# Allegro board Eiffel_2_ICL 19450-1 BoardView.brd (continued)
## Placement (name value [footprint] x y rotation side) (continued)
R24006  10KR2F-2-GP  [R402H16]  70.95 9.16 0 bottom
R24007  10KR2F-2-GP  [R402H16]  77.86 18.36 0 bottom
R24008  33R2J-2-GP  [R402H16]  88.98 7.2 270 bottom
R24009  0R0402-PAD-2-GP  [0R0402-PAD-1]  87.37 20.84 180 bottom
R24010  17K8R2F-GP  [R402H16]  76.14 28.77 180 top
R24011  10KR2J-3-GP  [R402H16]  70.97 20.56 270 top
R24012  0R2J-2-GP  [R402H16]  97.81 10.76 90 top
R24013  10KR2J-3-GP  [R402H16]  70.97 19.51 90 top
R24014  1KR2F-3-GP  [R402H16]  83.37 18.28 90 bottom
R24015  0R2J-2-GP  [R402H16]  78.55 29.84 90 bottom
R24016  0R2J-2-GP  [R402H16]  85.97 23.73 0 bottom
R24017  10KR2J-3-GP  [R402H16]  81.84 28.77 270 bottom
R24018  100KR2J-1-GP  [R402H16]  73.26 22.34 180 bottom
R24019  0R2J-2-GP  [R402H16]  84.81 9.85 180 bottom
R24020  10KR2F-2-GP  [R402H16]  77.22 16.23 270 bottom
R24021  10KR2J-3-GP  [R402H16]  96.14 15.52 90 top
R24022  0R0402-PAD-2-GP  [0R0402-PAD-1]  84.53 28.4 180 top
R24023  0R2J-2-GP  [R402H16]  93.07 23.23 90 top
R24024  0R0402-PAD-2-GP  [0R0402-PAD-1]  95.49 12.99 270 top
R24025  0R0402-PAD-2-GP  [0R0402-PAD-1]  95.49 11.89 270 top
R24026  100R2F-L1-GP-U  [R402H14]  73.46 28.27 270 bottom
R24027  SCD1U16V2KX-3GP  [C402H22]  76.85 20.6 180 bottom
R24028  10KR2J-3-GP  [R402H16]  80.8 5.68 270 bottom
R24029  1KR2J-1-GP  [R402H16]  92.19 24.51 270 bottom
R24030  10KR2J-3-GP  [R402H16]  71.05 6.13 0 bottom
R24031  0R0402-PAD-2-GP  [0R0402-PAD-1]  74.47 5.42 180 top
R24032  0R0402-PAD-2-GP  [0R0402-PAD-1]  96.85 6 180 top
R24033  0R0402-PAD-2-GP  [0R0402-PAD-1]  86.32 20.84 180 bottom
R24034  0R0402-PAD-2-GP  [0R0402-PAD-1]  98.31 16.37 270 top
R24035  0R0805-PAD-2-GP-U  [0R0805-PAD-1-U]  82.14 8.86 180 bottom
R24036  0R0402-PAD-2-GP  [0R0402-PAD-1]  95.49 14.09 270 top
R24037  0R0402-PAD-2-GP  [0R0402-PAD-1]  85.19 20.84 180 bottom
R24038  10KR2J-3-GP  [R402H16]  78.9 5.55 90 bottom
R24039  10KR2J-3-GP  [R402H16]  84.25 7.89 180 bottom
R24040  0R0402-PAD-2-GP  [0R0402-PAD-1]  86.06 5.99 0 bottom
R24041  0R2J-2-GP  [R402H16]  75.56 5.42 180 top
R24042  0R2J-2-GP  [R402H16]  93.5 22.15 90 top
R24044  10KR2J-3-GP  [R402H16]  89.88 28.98 180 top
R24045  10KR2F-2-GP  [R402H16]  82.07 12.42 180 bottom
R24046  10KR2F-2-GP  [R402H16]  78.03 24.49 90 bottom
R24047  0R2J-2-GP  [R402H16]  97.8 11.88 90 top
R24048  10KR2J-3-GP  [R402H16]  89.89 20.26 90 bottom
R24049  10KR2J-3-GP  [R402H16]  89.89 21.32 90 bottom
R24051  330R2J-3-GP  [R402H16]  80.57 29.75 90 top
R24052  0R2J-2-GP  [R402H16]  97.79 9.65 90 top
R24053  0R2J-2-GP  [R402H16]  96.16 21.09 90 top
R24054  10KR2F-2-GP  [R402H16]  73.24 16.3 90 bottom
R24055  10KR2J-3-GP  [R402H16]  71.55 17.28 270 top
R24056  10KR2J-3-GP  [R402H16]  84.97 17.88 180 bottom
R24057  0R0402-PAD-2-GP  [0R0402-PAD-1]  86.62 29.9 180 top
R24058  0R0402-PAD-2-GP  [0R0402-PAD-1]  99.99 19.12 180 bottom
R24059  10KR2J-3-GP  [R402H16]  96 23.67 270 top
R24060  1KR2J-1-GP  [R402H16]  80.14 9.96 270 bottom
R24061  10KR2F-2-GP  [R402H16]  74.08 27.06 90 top
R24062  20KR2J-L2-GP  [R402H16]  94.93 6.01 180 top
R24063  10KR2J-3-GP  [R402H16]  85.06 29.94 90 top
R24064  33R2J-2-GP  [R402H16]  96.15 16.55 90 top
R24065  10KR2J-3-GP  [R402H16]  70.97 21.63 270 top
R24066  4K7R2J-2-GP  [R402H16]  88.25 24.46 180 bottom
R24067  0R2J-2-GP  [R402H16]  84.5 25.17 270 bottom
R24068  0R0402-PAD-2-GP  [0R0402-PAD-1]  90.93 28.4 180 top
R24069  10KR2J-3-GP  [R402H16]  85.98 9.87 0 bottom
R24070  0R2J-2-GP  [R402H16]  81.29 5.25 180 top
R24071  10KR2J-3-GP  [R402H16]  78.9 6.57 90 bottom
R24072  10KR2J-3-GP  [R402H16]  70.6 7.61 270 bottom
R24073  10KR2F-2-GP  [R402H16]  78.7 20.61 180 bottom
R24074  0R0402-PAD-2-GP  [0R0402-PAD-1]  72 25.62 270 top
R24075  10KR2J-3-GP  [R402H16]  70.89 11.64 270 top
R24076  10KR2F-2-GP  [R402H16]  79.9 13.47 90 bottom
R24077  10KR2F-2-GP  [R402H16]  80.84 18.37 0 bottom
R24078  10KR2J-3-GP  [R402H16]  88.81 28.98 180 top
R24079  10KR2J-3-GP  [R402H16]  96.06 8.11 0 top
R24081  0R2J-2-GP  [R402H16]  76.6 6 180 top
R24082  0R0402-PAD-2-GP  [0R0402-PAD-1]  95.45 10.77 270 top
R24084  10KR2J-3-GP  [R402H16]  70.96 22.69 90 top
R24085  0R0402-PAD-2-GP  [0R0402-PAD-1]  95.45 9.66 270 top
R24086  10KR2F-2-GP  [R402H16]  72.53 7.64 270 bottom
R24087  0R2J-2-GP  [R402H16]  98.35 20.84 180 top
R24088  4K7R2J-2-GP  [R402H16]  98.47 18.74 90 bottom
R24089  33R2J-2-GP  [R402H16]  87.37 6.15 0 bottom
R24091  0R0402-PAD-2-GP  [0R0402-PAD-1]  76.4 18.76 90 bottom
R24092  0R2J-2-GP  [R402H16]  97.81 14.01 90 top
R24093  0R2J-2-GP  [R402H16]  97.81 12.97 90 top
R24094  0R0402-PAD-2-GP  [0R0402-PAD-1]  73.02 7.42 270 top
R24095  10KR2J-3-GP  [R402H16]  97.63 18.99 90 top
R24096  95K3R2F-GP  [R402H16]  74.35 29.22 270 top
R24097  20KR2J-L2-GP  [R402H16]  71.73 21.89 90 bottom
R24098  10KR2F-2-GP  [R402H16]  79.8 18.38 0 bottom
R24099  10KR2J-3-GP  [R402H16]  85.58 28.4 180 top
R24100  4K7R2F-GP  [R402H16]  70.68 18.61 180 bottom
R24101  10KR2J-3-GP  [R402H16]  70.97 18.44 90 top
R24102  33R2J-2-GP  [R402H16]  84.99 6.01 180 bottom
R24103  0R5J-5-GP  [R805H24]  89.6 17.85 0 bottom
R24104  100KR2J-1-GP  [R402H16]  97.56 17.97 270 top
R24105  33R2J-2-GP  [R402H16]  91.48 5.98 270 bottom
R24106  33R2J-2-GP  [R402H16]  88.99 6.16 90 bottom
R24107  1KR2J-1-GP  [R402H16]  79.05 30.16 180 top
R24108  10KR2J-3-GP  [R402H16]  89.89 22.4 90 bottom
R24109  10KR2F-2-GP  [R402H16]  69.1 9.17 0 bottom
R24110  100KR2J-1-GP  [R402H16]  96 22.64 90 top
R24111  10KR2J-3-GP  [R402H16]  89.99 14.64 270 bottom
R24112  1KR2J-1-GP  [R402H16]  91.91 7.5 180 bottom
R24113  0R0402-PAD-2-GP  [0R0402-PAD-1]  82.55 29.42 180 top
R24114  10KR2F-2-GP  [R402H16]  79.74 28.81 90 bottom
R24115  10KR2F-2-GP  [R402H16]  80.24 11.29 90 bottom
R24116  10KR2J-3-GP  [R402H16]  95 8.11 0 top
R24117  4K7R2J-2-GP  [R402H16]  95.03 23.38 270 bottom
R24118  4K7R2J-2-GP  [R402H16]  95.69 25.74 270 top
R24119  0R0402-PAD-2-GP  [0R0402-PAD-1]  95.69 26.78 90 top
R24120  0R0402-PAD-2-GP  [0R0402-PAD-1]  91.47 26.97 180 bottom
R24121  10KR2J-3-GP  [R402H16]  70.42 16.24 270 top
R24924  499R2F-2-GP  [R402H16]  169.1 74.09 270 bottom
RC4502  SCD1U25V2KX-L-GP  [C402H22]  101.57 77.36 90 top
RJ1  SKT-RJ45-LED-60-GP  [23-01122-2A03-B]  70.5 47.05 180 top
RN303  SRN51J-GP  [SMD-ARES4H18]  170 68.42 0 bottom
RN1201  SRN1KJ-7-GP  [SMD-ARES4H18]  256.01 33.58 180 bottom
RN1301  SRN1KJ-7-GP  [SMD-ARES4H18]  241.01 32.5 180 bottom
RN1804  SRN20KJ-1-GP  [SMD-ARES4H20]  204.05 19.12 180 bottom
RN1810  SRN2K2J-1-GP  [ARES2H16]  173.87 10.94 0 bottom
RN1811  SRN2K2J-1-GP  [ARES2H16]  176.83 6.6 270 top
RN1812  SRN2K2J-4-GP  [ARES8-CN24-UH20]  169.32 20.11 270 bottom
RN1914  SRN2K2J-1-GP  [ARES2H16]  198.24 16.52 90 bottom
RN1915  SRN2K2J-1-GP  [ARES2H16]  198.24 14.34 90 bottom
RN2201  SRN100KJ-6-GP  [SMD-ARES4]  186.4 6.89 0 bottom
RN2402  SRN10KJ-5-GP  [ARES2H18]  92.93 29.8 90 bottom
RN2403  SRN10KJ-5-GP  [ARES2H18]  70.95 13.7 0 top
RN2404  SRN10KJ-5-GP  [ARES2H18]  87.05 17.8 270 bottom
RN2405  SRN10KJ-5-GP  [ARES2H18]  88.08 9.23 270 bottom
RN2703  SRN4K7J-8-GP  [SMD-ARES4H18]  29.64 80.86 270 top
RN4001  SRN10KJ-5-GP  [ARES2H18]  215.59 9.02 90 bottom
RN4002  SRN10KJ-5-GP  [ARES2H18]  203.62 75.55 270 bottom
RN5702  SRN2K2J-5-GP  [SMD-ARES4H18]  41.02 59.56 90 bottom
RN6119  SRN10KJ-5-GP  [ARES2H18]  130.8 9.65 90 top
RN6120  SRN47K-2-GP-U  [SMD-ARES4H18]  102.63 11.27 180 top
RT2401  NTC-10K-19-GP-U  [NTC-402H22-U]  132.79 58.38 90 top
RT2402  NTC-10K-19-GP-U  [NTC-402H22-U]  80.56 28.65 90 top
SATA1  SKT-SATA7P-15P-163-GP  [C166KK-12209-L]  2.8 63.5 270 top
SPK1  ACES-CON4-95-GP  [87212-0044N-W01]  4 15 270 top
TP602  TPAD28-2-GP  [TPAD28]  174.01 51.61 270 bottom
TP603  TPAD28-2-GP  [TPAD28]  173.8 49.64 270 bottom
TP604  TPAD28-2-GP  [TPAD28]  176.06 51.97 180 bottom
TP605  TPAD28-2-GP  [TPAD28]  175.8 50.06 270 bottom
TP607  TPAD28-2-GP  [TPAD28]  181.67 33.69 180 bottom
TP608  TPAD28-2-GP  [TPAD28]  166.22 74.4 270 top
TP609  TPAD28-2-GP  [TPAD28]  164.56 74.4 270 top
TP619  TPAD28-2-GP  [TPAD28]  174.88 32.13 270 bottom
TP808  TPAD28-2-GP  [TPAD28]  170.72 63.12 180 bottom
TP1611  TPAD28-2-GP  [TPAD28]  191.48 36.76 180 bottom
TP1702  TPAD28-2-GP  [TPAD28]  167.86 41.04 180 bottom
TP2111  TPAD28-2-GP  [TPAD28]  182.45 26.69 180 bottom
TP4402  TPAD14-OP-GP  [TPAD14-OP]  104.59 12.19 0 top
TP9901  TPAD28-2-GP  [TPAD28]  171.63 67.94 180 bottom
TP9902  TPAD28-2-GP  [TPAD28]  172.97 66.11 180 bottom
TP9904  TPAD28-2-GP  [TPAD28]  178.51 29.83 180 bottom
TP9905  TPAD28-2-GP  [TPAD28]  162.09 70.11 0 top
TP9906  TPAD28-2-GP  [TPAD28]  168.96 65.93 180 bottom
TP9907  TPAD28-2-GP  [TPAD28]  170.16 64.82 180 bottom
TP9908  TPAD28-2-GP  [TPAD28]  166.1 68.22 0 top
TP9909  TPAD28-2-GP  [TPAD28]  168.87 64.56 180 bottom
TP9910  TPAD28-2-GP  [TPAD28]  171.21 66.28 180 bottom
TSMT1  RTD2136N-CGT-GP  [QFN48J6-G4D55H40]  35.74 25.47 0 bottom
U2401  W25X10CLSNIG-GP  [SOIC8H69]  75.12 12.31 270 bottom
U2501  MX25L12872FM2I-10G-GP  [SOIC8-1H86]  200.18 9.79 90 top
U2504  SKT-91960-0084L-GP  [SKT-SOIC8-1H211]  200.18 9.79 270 top
U2601  APL5606AKI-TRG-GP  [SOIC8H69]  254.23 4.55 270 bottom
U2701  ALC256M-CG-GP  [QFN48J6-G465H40]  31.42 71.64 270 top
U3101  AZC199-04SDR7G-1-GP  [SOT-6-1H58]  68.25 68.26 180 top
U3102  AZC199-04SDR7G-1-GP  [SOT-6-1H58]  74.09 68.34 180 top
U3103  RT9742CGJ5-GP  [SOT-23-5H40]  58.39 77.36 180 top
U3301  RTS5176-GR-GP  [QFN24-G2D5H40-U]  36.39 95.74 0 bottom
U3401  RT9742CGJ5-GP  [SOT-23-5H40]  37.36 57.56 0 top
U3402  RT9742CGJ5-GP  [SOT-23-5H40]  40.93 56.55 0 top
U3503  RT9742CGJ5-GP  [SOT-23-5H40]  77.38 79.91 180 top
U3504  RT9742CGJ5-GP  [SOT-23-5H40]  200.6 96.32 270 top
U4003  TPS22976DPUR-GP  [SON14J3020-G2610H34]  46.28 82.01 180 bottom
U4007  G5027CRD1D-GP-U  [DFN8F3-G2517H32]  190.47 13.07 0 bottom
U4009  TC7SZ08FU-LJ-CT-GP  [SC70-5H44]  185.83 11.46 180 bottom
U4010  G5027CRD1D-GP-U  [DFN8F3-G2517H32]  151.71 23.77 90 bottom
U4011  G5027CRD1D-GP-U  [DFN8F3-G2517H32]  151.85 18.13 90 bottom
U4012  G5027CRD1D-GP-U  [DFN8F3-G2517H32]  162.1 47.6 90 top
U4013  74LVC1G07GW-GP  [SC70-5H44]  163.78 18.77 0 bottom
U4020  SN74AUP1G08DCKR-GP  [SC70-5H44]  117.86 17.86 270 bottom
U4303  INA199A3DCKR-GP  [SC70-6H44]  90.08 31.46 90 top
U5301  G5027CRD1D-GP-U  [DFN8F3-G2517H32]  19 79.96 90 top
U5501  OZ554LN-A-0-TR-GP  [QFN20-G2D1H34]  18.65 28.65 270 top
U5504  RT9742CGJ5-GP  [SOT-23-5H40]  66.75 17.89 180 bottom
U5602  M24C64-RMN6TP-2-GP  [SOIC8H69]  53.35 15.5 270 bottom
USB3R1  SKT-USB11-153-GP  [SKT-USB11-138166]  60 97.08 180 top
USB3R2  SKT-USB11-153-GP  [SKT-USB11-138166]  189 97.08 180 top
USB3R3  SKT-USB11-267-GP  [SKT-USB11-160090-3-U]  30.94 41.04 270 top
USB3R4  SKT-USB11-267-GP  [SKT-USB11-160090-3-U]  42.44 41.04 270 top
X1801  XTAL-32D768KHZ-98-GP  [SMD49-12H34]  195.39 21.01 90 bottom
X1802  XTAL-38D4MHZ-28-GP  [OSC-3225-4P-4H36]  172.68 15.93 0 top
X3101  XTAL-25MHZ-359-GP  [SMD-OSC38H32]  70.99 80.94 270 bottom
XF3101  XFORM-24P-19-GP  [XFORM24C1510H168]  70.78 59.55 0 top

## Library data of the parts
AUDS1 = J1100D-C6DH-0002R: tolerance: 022.10002.0C41
BTT1 = 40-42087-00211RHF-WH-U1: tolerance: 062.70001.0081
C501 C1271 C1281 C1302 C1338 C2202 C2214 C2502 C2707 C2709 C2710 C2716 C2719 C2725 C4030 PC5110 PC5406 PC5407 = C402H22: tolerance: 78.10421.L0L
C701 C2217 C2424 C2503 C4048 C4049 C4302 C4303 C5503 C5510 C5512 C6105-C6107 C6109 EC6901-EC6905 EC6918-EC6923 FC9085-FC9092 PC4501 PC4505 PC4511-PC4515 PC4601 PC4604 PC4607-PC4611 PC5003-PC5005 PC5013 PC5101 PC5111 PC5205 PC5314 PC5320 PC5404 PC5405 = C402H22: tolerance: 78.10422.5FL
C702 C1325 C2218 C2403 C2417 C2423 C2605 C5501 C5506 PC4612 PC5204 = C402H22: tolerance: 78.10134.1FL
C703 C2219 = C402H24: tolerance: 78.12034.1FL
C1101 C1109-C1113 C2706 C2708 C2711 C4011 C4014 C4053 C4060 C4070 C4085 C5303 C5550 C5611 C6104 C6108 C6304 C6342 = C603H38: tolerance: 78.10610.5BL
C1102-C1107 C1114 C1115 C1119-C1122 C1125-C1129 C1216-C1220 C1222 C1223 C1235-C1237 C1251 C1252 C1314 C1315 C1319 C1322 C1331-C1336 C1340 C1341 C1820 C1821 C2204 C2206 C2215 C2418 C2419 C2421 C2422 C2425 C2507 C3141 C3155 C3301 C3302 C3405 C3515 C3524 C4009 C4012 C4015-C4017 C4024 C4069 C4093 C5301 C5527 C5554 PC5103 PC5108 PC5109 PC5116 PC5206 PC5401 = C402H22: tolerance: 78.10523.5FL
C1108 = C603H40: tolerance: 78.4761T.5BL
C1116-C1118 C2405 C2408 C2420 C2603 C3004 C3153 C3404 C3407 C3409 C3417 C3418 C3423 C3517 C3518 C3520 C3522 C3523 C3526 C5556 C5616 PC1002-PC1014 PC1026-PC1032 PC1042-PC1059 PC5117-PC5122 PC5201-PC5203 PC5301 PC5303 PC5305-PC5307 = C603H40: tolerance: 78.22610.5BL
C1205-C1209 C1213-C1215 C1232 C1234 C1238 C1250 C1312 C1313 C1316-C1318 C1320 C1321 C1327 C1329 C1330 C1342 C1343 C2501 C2702 C2712-C2714 C2717 C2718 C2720 PC5402 PC5403 PC5410-PC5412 = C603H38: tolerance: 78.10610.L0L
C1221 C1328 = C402H22: tolerance: 78.22321.2FL
C1272 C1339 C2213 C2703-C2705 PC4603 = C603H36: tolerance: 78.22523.L1L
C1701 C1705 C1823 C2207 C2402 C2404 C2406 C2407 C2409-C2416 C2426 C2427 C2602 C2907 C2908 C2910 C3002 C3005 C3006 C3103 C3106 C3118 C3119 C3128-C3134 C3137-C3140 C3142 C3143 C3145 C3146 C3151 C3154 C3304 C3306 C3308 C3312-C3314 C3406 C3411-C3416 C3513 C3514 C3516 C3521 C4001 C4013 C4018-C4020 C4025 C4501 C4502 C5304 C5528 C5545 C5551 C5559 C5601-C5607 C5609 C5610 C5612-C5615 C5618-C5620 C5701-C5705 C5707-C5709 C5714 C5721 C5722 C6001 C6101 C6102 C6303 C6305 C6341 C6345 EC6906-EC6910 EC6913-EC6917 PC5207 R24027 = C402H22: tolerance: 78.10421.2FL
C1801 C1802 = C402H22: tolerance: 77P4825AA
C1805 C1806 = C402H22: tolerance: 78.15034.1FL
C1904 C2726 = C402H22: tolerance: 78.33034.1FL
C2201 C2203 C2208-C2212 PC5001 PC5002 = C402H22: tolerance: 78.10523.L2L
C2205 C2601 C2604 C3007 C3102 C3135 C3136 C3147 C3303 C3305 C3307 C3309 PC5302 = C603H36: tolerance: 78.47520.5BL
C2216 = C603H40: tolerance: 078.47610.05BL
C2401 = C603H36: tolerance: 78.22523.5BL
C2701 C2715 C2723 C2724 PC4602 = C603H36: tolerance: 78.47520.L0L
C2911 PC5010 = C402H22: tolerance: 78.22224.2FL
C3001 C5505 C5520 C6003-C6006 C6401 = C402H22: tolerance: 78.10324.2FL
C3008 C3009 C6103 C6301 = C402H22: tolerance: 78.10034.1FL
C3125 = C1206H71: tolerance: 78.1022S.22L
C3126 C3127 FC9001-FC9012 PC5112 = C402H22: tolerance: 78.18034.1FL
C3152 C4007 C4008 C4304 C5515 EC2902-EC2905 EC5501-EC5503 EC6401 EC6402 PC5104 = C402H22: tolerance: 78.10224.2FL
C3401 EC4302 PC4302 = C603H36: tolerance: 78.10424.2BL
C3501 C3502 = C402H22: tolerance: 78.22423.5FL
C4026 = C402H22: tolerance: 78.10421.2FLLL
C4061 C4062 C4072 C5302 = C402H22: tolerance: 78.10421.2FLDL
C5502 C5511 EC4301 PC4301 = C603H32: tolerance: 78.10524.5BL
C5504 = C805H54: tolerance: 78.47522.51L
C5507 C5508 C5513 C5514 C5516-C5519 C5521-C5526 C5529-C5534 EC3321-EC3328 = C402H22: tolerance: 78.5R074.1FL
C5509 PC4606 = C603H36: tolerance: 78.47422.5BL
C5536 C5541 C5608 C5617 C6002 PC4502-PC4504 PC4506-PC4510 PC5006-PC5008 PC5102 PC5105-PC5107 PC5114 PC5115 PC5315 PC5316 = C805H56: tolerance: 78.10622.51L
C5537-C5540 C5542 = C1206H71: tolerance: 78.10525.22L
C5544 = C603H36: tolerance: 78.33135.1BL
C5621 PC4516 PC4517 = C402-TO0D2H26: tolerance: 78.47510.5FL
C5713 PC5011 = C402H22: tolerance: 78.47124.2FL
C6306-C6311 C6331 C6332 = C402H22: tolerance: 78.22423.L2L
CAM1 = 51290-0084N-W01: tolerance: 020.F1064.0008
CMOS1 = SKRBAJF010: tolerance: 62.40089.071
CNVBD1 = 51290-0124N-W01: tolerance: 020.F1064.0012
CPU1 = BGA1526M2550-1H51: tolerance: ZZ.00CPU.221
CRS1 = 156-5001902601: tolerance: 62.10051.H51
D2401-D2403 D2701 ED2901-ED2905 = SOT23-2D4-312H46: tolerance: 75.05125.07D
D2501 D4004 D4005 = SOT23-2D4-312H44: tolerance: 75.00054.T7D
D3101 = SOD323AKH38: tolerance: 83.R5003.H8H
D3102 = SOD-523-4H28: tolerance: 75.05125.070
D4302 = SOT-323H40: tolerance: 83.00070.F11
D5301 = SOD323AKH38: tolerance: 83.00355.D1F
D5501 = D4724AKH44: tolerance: 83.3R010.C8M
D5701 = SOT23-2D4-312H44: tolerance: 75.00056.07D
D6301 D6903 D6904 ED6902 = SOD882-10D6-1H20: tolerance: 83.05725.0A0
DBGH1 = 50228-0147N-W01: tolerance: 20.F1637.014
DCIN1 = 2DC3012-005111F: tolerance: 022.10015.0481
DIMM1 = ASAA821-E8RB0-7H: tolerance: 062.10011.01G1
DIMM2 = ASAA821-H4RB5-7H: tolerance: 062.10011.0P91
EC1720 = C402H22: tolerance: 78.22034.L1L
EC1801 EC1802 PC5012 = C402H22: tolerance: 78.22034.1FL
EC2909-EC2913 PC4701 PC4708 = C402H22: tolerance: 78.10224.L1L
EC3101-EC3108 = C402H22: tolerance: 78.6R074.1FL
ECIO1 = LQFP128H63: tolerance: 071.08637.000G
ED3002 ED3401 ED3502 ED3505 ED6101 = SOT-6H58: tolerance: 075.53456.000C
ED3101-ED3103 = SOT23-2D4-312H44: tolerance: 75.00099.O7D
ED3402 ED3403 ED3501 ED3504 ED5701 ED5702 ED6001 = DFN10G2510H22: tolerance: 075.01043.0073
ED4301 = DO214AAAK-1121H97: tolerance: 83.P6SMB.AAG
ED5703 = SOT-6H58: tolerance: 075.09904.0A7C
EL3001 EL3401 EL3402 EL3503 EL3509 EL6103 = DUMMY-LD65D85-4PH20: tolerance: ZZ.PAD02.091
EL3403-EL3406 EL3501 EL3502 EL3507 EL3508 EL5701-EL5704 EL6001 EL6002 = L125100-4P-5H24: tolerance: 68.24500.201
ER1801 ER1802 PR4511 PR4634 PR4636 PR5113 PR5114 PR5317 PR5326 PR5401 PR5413 PR5423 R511 R706 R809 R1302 R1510 R1709 R1720 R1722 R1727 R2204 R2208 R2519 R2605 R2702-R2706 R2710 R2721 R2722 R2732 R2733 R2754 R2766 R2909 R2922-R2924 R3115 R3141 R3142 R3154 R3303-R3305 R4014 R4018 R4035 R4047 R4051 R4054 R4602-R4604 R5536 R5601 R5607 R5625 R5626 R5731 R6105 R6107 R6109 R6110 R6133 R6134 R6141 R6302 R6303 R6311 R6313 R6314 R10013 R10014 R10021 R24004 R24009 R24022 R24024 R24025 R24031-R24034 R24036 R24037 R24040 R24057 R24058 R24068 R24074 R24082 R24085 R24091 R24094 R24113 R24119 R24120 = 0R0402-PAD-1: tolerance: ZZ.00PAD.M11
F3001 F3002 F5701 = POLYSW-2114H30: tolerance: 69.48001.081
F5501 = POLYSW-4633-UH43: tolerance: 69.50007.A31
F6001 = POLYSW-2114H30: tolerance: 069.50003.0001
FANC1 = 3801-Q03S-01R: tolerance: 20.D0246.103
G2401 G6401 = CON2C-U: tolerance: ZZ.CON2C.XXX
G2530 = CON2O-U: tolerance: ZZ.CON2O.XXX
GDT1 = TVS5436-1121H105: tolerance: 069.A0007.0001
H1-H5 = GEN315R158-8-F-C-S-U: tolerance: ZZ.SCREW.541
HDMI1 = SKT-HDMI22-148070: tolerance: 062.10012.0401
HS5 = STF256R109H124: tolerance: 334.0350J.0001
HS6 = STF256R113-UH286: tolerance: 334.08002.0001
HS7 = STF236R128H34: tolerance: 34.4QP10.001
L2401 L2903-L2907 L2910 L3302 L6405 L6406 = L402-TO0D2H24: tolerance: 068.00049.0041
L3101 = L3030-3009-2H40: tolerance: 68.4R71H.10H
L3102-L3105 L3301 = L125100-4P-4H24: tolerance: 68.00396.001
L5501 = L125100-4P-1H37: tolerance: 68.01012.201
L5502 = L8080-6020H158: tolerance: 068.33010.1061
L5601 L5602 = L402H24: tolerance: 068.00005.0051
L6401 = L603H38: tolerance: 68.00335.091
LAN1 = QFN32J4-G2D85H36: tolerance: 71.08111.U03
LED1 = LED3020-3P-6H44: tolerance: 83.01222.X80
LED683-LED685 = LED1608-1A2KH40: tolerance: 83.01921.S70
LVDS1 = 50524-0300N-001: tolerance: 020.K0037.0030
MFG1 = MSS3-Q-T-R: tolerance: 62.40018.641
NGFFE1 = AS0BC21-S40BE-7H: tolerance: 062.10003.0611
NGFFM1 = APCI0096-P003A: tolerance: 062.10003.0E81
PC4605 = C603H40: tolerance: 78.22422.2BL
PC4613 PC5312 = C402H22: tolerance: 78.22124.2FL
PC4624 PC5308 RC4502 = C402H22: tolerance: 78.10422.L1L
PC4702-PC4707 PC4709 PC4710 = C805H56: tolerance: 78.10622.LAL
PC5113 = C402H22: tolerance: 78.47322.2FL
PC5313 = C402H22: tolerance: 78.10322.2FL
PG4501-PG4514 PG4516-PG4518 PG4520 PG4529-PG4533 PG4601 PG4701-PG4712 PG5001-PG5006 PG5101-PG5104 PG5201-PG5204 PG5301 PG5302 PG5304 PG5305 PG5315 PG5318 PG5320 PG5401 PG5402 = GAP-CLOSE-PWR-3: tolerance: ZZ.CLOSE.001
PL4501 PL4502 = L7066-1830-UH119: tolerance: 68.2R210.20B
PL4701 PL4702 PL5001 = L7366-1930H158: tolerance: 68.R1510.20A
PL5101 = L7066-1830-UH119: tolerance: 68.1R01A.20B
PL5301 = L4947-1115H119: tolerance: 68.1R010.20R
PL5401 = L2520-D620H48: tolerance: 068.1R010.1131
PL5402 = L2520-D620H48: tolerance: 68.1001S.10K
PR4301 R1820 = R402H16: tolerance: 64.20035.6DL
PR4302 PR4303 R5505 R24062 R24097 = R402H16: tolerance: 63.20334.1DL
PR4304 PR5110 PR5204 PR5420 PR5421 R403 R1503 R1504 R1506 R1507 R1531 R1534 R1706 R1712 R1713 R1718 R1726 R1728 R1729 R1840-R1844 R2108 R2201 R2209 R2210 R3404 R4052 R4053 R4057 R5602 R5624 R5730 R24018 R24104 R24110 = R402H16: tolerance: 63.10434.1DL
PR4305 = R2512H32: tolerance: 64.R0105.97L
PR4501 PR4502 PR4605 PR4609 PR4612 PR4616 PR5007 PR5109 = R603H22: tolerance: 64.2R205.55L
PR4503 = R402H16: tolerance: 64.11835.6DL
PR4504 = R402H16: tolerance: 64.84525.6DL
PR4505 = R402H16: tolerance: 64.68015.6DL
PR4506 R3161 = R402H16: tolerance: 64.15025.6DL
PR4507 PR4508 PR4641 PR5013 PR5201 PR5407 R2031 R2041 R5507 R5511 R5518 R5519 R24006 R24007 R24020 R24045 R24046 R24054 R24061 R24073 R24076 R24077 R24086 R24098 R24109 R24114 R24115 = R402H16: tolerance: 64.10025.6DL
PR4509 PR4510 PR5003 PR5005 PR5006 PR5202 PR5327 R1821 R3311 R4320 R5514 = R402H16: tolerance: 64.10035.6DL
PR4601 = R402H16: tolerance: 64.26725.6DL
PR4604 = R805H24: tolerance: 64.6R205.16L
PR4607 PR4637 PR5304 R2003 R2730 = R402H15: tolerance: 64.10025.L0L
PR4613 PR4630 = R402H16: tolerance: 64.75R05.6DL
PR4615 = R402H16: tolerance: 64.3R905.6DL
PR4619 = R402H16: tolerance: 64.35715.6DL
PR4620 = R402H16: tolerance: 64.12115.6DL
PR4621 = R402H16: tolerance: 64.90915.6DL
PR4622 = R402H16: tolerance: 64.12425.6DL
PR4624 = R402H16: tolerance: 64.34815.6DL
PR4625 = R402H16: tolerance: 64.11815.6DL
PR4626 = R402H16: tolerance: 64.82515.6DL
PR4627 = R402H16: tolerance: 64.24925.6DL
PR4628 PR4633 PR4646 PR4655 = R603H22: tolerance: 64.20015.55L
PR4629 PR4635 = R402H16: tolerance: 64.68005.6DL
PR4631 PR4638 PR4644 PR4660 PR4661 PR4667 PR4669 PR5017 PR5018 R311 R505-R507 R606 R704 R705 R708 R1601 R2103 R5508 R24026 = R402H14: tolerance: 64.10005.6DL
PR4632 = R402H16: tolerance: 64.45R35.6DL
PR4639 PR4702 = NTC-402H22-U: tolerance: 69.60011.221
PR4640 = R402H16: tolerance: 64.31625.6DL
PR4643 = R402H16: tolerance: 64.18725.6DL
PR4659 R1902 R1903 R2101 = R402H16: tolerance: 64.20005.6DL
PR4662 PR4663 = R402H16: tolerance: 64.46415.6DL
PR4665 = R402H16: tolerance: 64.28715.6DL
PR4666 = R402H16: tolerance: 64.35705.6DL
PR4668 R5506 = R402H14: tolerance: 64.10R05.6DL
PR4671 PR4672 PR4674 PR4677 PR4688 PR5002 PR5012 PR5016 PR5034 PR5035 PR5052 PR5120 PR5410 PR5419 PR5422 R4016 R4037 = 0R0402-PAD: tolerance: ZZ.R0402.001
PR4701 = R402H16: tolerance: 64.11035.6DL
PR4704 PR4705 = R1206H28: tolerance: 63.2R232.11L
PR5001 = R603H22: tolerance: 63.5R133.15L
PR5004 = R402H18: tolerance: 064.71535.06D1
PR5008 R24010 = R402H16: tolerance: 64.17825.6DL
PR5009 PR5010 = R402H16: tolerance: 63.1R034.1DL
PR5011 = NTC-402H22-U: tolerance: 69.60011.201
PR5014 = R402H16: tolerance: 64.34015.6DL
PR5015 = R402H16: tolerance: 64.56215.6DL
PR5033 = R603H22: tolerance: 63.1R033.15L
PR5105 PR5115 = R805H24: tolerance: 63.2R231.16L
PR5106 = R402H16: tolerance: 64.19135.6DL
PR5108 = R402H16: tolerance: 64.5R105.6DL
PR5111 = R402H16: tolerance: 64.75035.6DL
PR5116 R2104 R2105 R4002 = R402H16: tolerance: 64.20025.6DL
PR5117 = R402H16: tolerance: 64.15825.6DL
PR5203 = R402H16: tolerance: 64.21525.6DL
PR5301 = R402H16: tolerance: 64.82025.6DL
PR5302 = R402H16: tolerance: 64.12725.6DL
PR5303 R2709 R2711 R4003 R4038 = R402H16: tolerance: 64.10035.L3L
PR5325 PR5331 R1914 R1915 R3106 R3160 R4004 R4012 R4044 R5301 R5504 R5509 R5627 R24029 R24060 R24107 R24112 = R402H16: tolerance: 63.10234.1DL
PR5402 PR5403 PR5405 R2902 = 0R0402-PAD: tolerance: ZZ.R0402.ZZZ
PR5408 = R402H16: tolerance: 64.75015.6DL
PT4501 = CT7343H83: tolerance: 79.15710.90L
PT4502 = SE331721H237: tolerance: 79.22710.E0L
PT4701 PT5001 = CT7343H83: tolerance: 79.3371V.2PL
PT4703 PT5002 = CT7343H79: tolerance: 077.23361.0001
PU4301 = SOIC8H69: tolerance: 084.04305.0037
PU4501 PU4502 = PPAK-8P-3333-2H40: tolerance: 084.03434.0037
PU4503 = QFN20-G1D75H32: tolerance: 074.06575.0A43
PU4504 PU4505 = PPAK-8P-3333-1H40: tolerance: 084.03432.0037
PU4601 = QFN32J4-G2D75H32: tolerance: 074.03612.0B73
PU4701-PU4704 = PPAK-8P-G5324H44-COLAY: tolerance: ZZ.00215.037
PU5001 = QFN20-G1D75H32: tolerance: 074.06543.0073
PU5002 PU5005 = PPAK-5PH48: tolerance: 084.00600.0B37
PU5003 PU5004 = PPAK-5PH48: tolerance: 084.006B0.0037
PU5101 = PPAK-8PH48: tolerance: 084.04378.0037
PU5102 = PPAK-8PH48: tolerance: 084.04504.0037
PU5103 = QFN20-G1D75H32: tolerance: 074.08231.0073
PU5201 = SOIC8-G3530H63: tolerance: 74.05930.B3D
PU5301 = QFN22G4-G2P-1H36: tolerance: 074.05335.0A43
PU5401 = QFN16G3-G2H34: tolerance: 074.08738.0073
PWRBT1 = TA2-32N-Q-T-R: tolerance: 062.40001.0B51
Q1801 Q2403 Q3401 Q4001 Q4004 Q5701 = SOT-363H44: tolerance: 75.27002.F7C
Q1820 Q2401 Q2402 Q2404 Q2501 Q3111 Q3402 Q4007 Q4301 Q4308 Q5702 Q5705 Q6805 = SOT23DGS2D4H44: tolerance: 84.2N702.J31
Q1901 Q6401 = SOT-23-10H44: tolerance: 84.03906.F11
Q1904 = SOT-363H44: tolerance: 075.00138.0A7C
Q4006 Q4009 Q4012 = SOT-363-1H44: tolerance: 75.03904.D7C
Q4013 = SOT23CBE2D4H44: tolerance: 84.T3904.H11
Q5506 = SOIC8H75: tolerance: 084.PA010.0037
Q6402 = SOT23DGS2D4H44: tolerance: 084.07002.0C31
Q6801 Q6803 = SOT23DGS2D4H44: tolerance: 084.03413.0031
R301 R313 = R402H16: tolerance: 63.51034.L0L
R302 R306 R1701 R2510 R5513 R24014 = R402H16: tolerance: 64.10015.6DL
R309 R310 R312 R605 R2106 R2107 = R402H16: tolerance: 64.49R95.6DL
R325 R1916 R1920 R2601 R2604 R2701 R2712 R2731 R2767 R3001 R3002 R3114 R4006 R4022 R4034 R4045 R4319 R4322 R4332 R4601 R5206 R5305 R5531 R5537 R5608 R5609 R5615 R5616 R6103 R6104 R6111 R6301 R6309 R6320 R24005 R24012 R24015 R24016 R24019 R24023 R24041 R24042 R24047 R24052 R24053 R24067 R24070 R24081 R24087 R24092 R24093 = R402H16: tolerance: 63.R0034.1DL
R401 R2102 R6802 R6806 R6807 = R402H16: tolerance: 64.15005.6DL
R402 = R402H16: tolerance: 64.15005.L0L
R510 R5701-R5703 R5706-R5710 = R402H16: tolerance: 64.47005.6DL
R607 R4036 = R402H15: tolerance: 63.10234.L0L
R702 R24002 = R402H15: tolerance: 64.43R05.6DL
R707 = R402H16: tolerance: 63.56034.1DL
R808 R2714 R2758 R2768 R3006 R3008 R3135 R3302 R5503 R6412 = 0R0603-PAD-1-U: tolerance: ZZ.00PAD.M21
R1214 R1305 = R402H16: tolerance: 64.2R005.6DL
R1215 R1306 = R402H16: tolerance: 64.24R95.6DL
R1231 R1303 = R402H16: tolerance: 64.24005.6DL
R1501 R1505 R1508 R1511 R1512 R1514 R1516 R1520 R1522 R1524 R1526 R1528 R1530 R1705 = R402H15: tolerance: 63.47234.L0L
R1502 R1513 R1517 R1521 R1523 R1525 R1527 R1529 = R402H16: tolerance: 64.20525.6DL
R1518 R1519 R1533 R1833 R2603 R2723 R5721 R5722 R6405 = R402H16: tolerance: 63.22234.1DL
R1532 R1608 R1714-R1717 R1730 R1732 R1746 R1812 R1813 R3116 R3143 R3144 R3401-R3403 R4011 R4013 R4020 R4026 R4027 R4033 R4326 R4331 R4501 R5522-R5524 R6112 R6160 R6305 R6308 R6310 R6402 R6403 R6410 R24001 R24011 R24013 R24017 R24021 R24028 R24030 R24038 R24039 R24044 R24048 R24049 R24055 R24056 R24059 R24063 R24065 R24069 R24071 R24072 R24075 R24078 R24079 R24084 R24095 R24099 R24101 R24108 R24111 R24116 R24121 = R402H16: tolerance: 63.10334.1DL
R1602 R1604-R1606 R2021 R2023 = R402H15: tolerance: 63.10334.L0L
R1603 = R402H16: tolerance: 64.11305.6DL
R1704 = R402H16: tolerance: 64.10045.6DL
R1804 R1805 R1823-R1827 = R402H16: tolerance: 63.51034.1DL
R1811 R3121 = R402H16: tolerance: 63.10634.1DL
R1818 = R402H16: tolerance: 64.75025.6DL
R1819 = R402H16: tolerance: 64.60R45.6DL
R1839 = R402H15: tolerance: 63.10434.L1L
R1901 R1904 R1905 R1919 R2718 R3003 R3004 = R402H15: tolerance: 63.33034.L0L
R1912 R1913 = R402H16: tolerance: 64.33R05.6DL
R2001 R2002 = R402H16: tolerance: 64.49925.6DLLS
R2206 = R402H16: tolerance: 064.R1005.06D1
R2508 = R402H16: tolerance: 64.33015.6DL
R2511 R5732 = R402H16: tolerance: 63.10534.1DL
R2514 = R402H16: tolerance: 64.45325.6DL
R2531 R2606 R4502 R5610-R5614 R5617 R5618 R6408 R24066 R24088 R24117 R24118 = R402H16: tolerance: 63.47234.1DL
R2602 = R402H16: tolerance: 63.22334.1DL
R2607 = R402H16: tolerance: 64.82015.6DL
R2713 = R402H16: tolerance: 64.20035.L4L
R2755 = 0R0603-PAD-U: tolerance: ZZ.R0603.001
R2759 R2769 R3005 R6411 = R603H22: tolerance: 63.00000.00L
R2778 = R402H15: tolerance: 63.47334.L0L
R2904 R2905 R6409 = R402H16: tolerance: 63.75034.1DL
R3102 = R402H16: tolerance: 64.24915.6DL
R3103 R5533 R5720 R24035 = 0R0805-PAD-1-U: tolerance: ZZ.00PAD.M31
R3107 R24103 = R805H24: tolerance: 63.R0031.16L
R3136 = R402H16: tolerance: 63.51134.1DL
R3138 R3139 R24051 = R402H16: tolerance: 63.33134.1DL
R3150 = R402H16: tolerance: 64.15015.6DL
R3151 R3152 = R402H16: tolerance: 64.24905.6DL
R3156-R3159 = R603H22: tolerance: 63.75033.15L
R3301 = R402H16: tolerance: 64.62015.6DL
R4005 = R402H16: tolerance: 064.60R45.C6D1
R4318 = R402H16: tolerance: 63.2R234.1DL
R4321 = R402H16: tolerance: 64.15035.6DL
R4324 R4325 = R402H16: tolerance: 64.1R005.6DL
R4327 = R402H16: tolerance: 64.69825.6DL
R5502 = 0R1206-PAD-1: tolerance: ZZ.R1206.ZZ1
R5510 R5512 = R402H14: tolerance: 63.10134.1DL
R5515 R5521 = R402H16: tolerance: 64.30035.6DL
R5532 = R805H24: tolerance: 63.1R031.16L
R5535 = R805H24: tolerance: 63.20131.16L
R5538 R5539 = R1206H26: tolerance: 64.R3305.41L
R5606 = R402H16: tolerance: 64.12025.6DL
R5619 R5620 R5622 R5623 = R402H16: tolerance: 63.10434.L0L
R5711-R5713 R5715 = R402H16: tolerance: 63.18134.1DL
R6108 R24008 R24064 R24089 R24102 R24105 R24106 = R402H16: tolerance: 63.33034.1DL
R6119 = R402H16: tolerance: 64.71525.6DL
R6120 = R402H16: tolerance: 64.10035.L1L
R6131 R6132 = R402H16: tolerance: 63.22034.L0L
R6404 = R805H24: tolerance: 63.30131.16L
R6407 = R805H24: tolerance: 63.15131.16L
R6801 R6810 = R402H15: tolerance: 63.R0034.L0L
R24003 = R402H16: tolerance: 64.64915.6DL
R24096 = R402H16: tolerance: 64.95325.6DL
R24100 = R402H16: tolerance: 64.47015.6DL
R24924 = R402H16: tolerance: 64.49905.6DL
RJ1 = 23-01122-2A03-B: tolerance: 062.10005.0371
RN303 = SMD-ARES4H18: tolerance: 66.51036.04L
RN1201 RN1301 = SMD-ARES4H18: tolerance: 66.10236.04L
RN1804 = SMD-ARES4H20: tolerance: 66.20336.04L
RN1810 RN1811 RN1914 RN1915 = ARES2H16: tolerance: 66.22236.04L
RN1812 = ARES8-CN24-UH20: tolerance: 66.22236.A8L
RN2201 = SMD-ARES4: tolerance: 66.10436.04L
RN2402-RN2405 RN4001 RN4002 RN6119 = ARES2H18: tolerance: 66.10336.04L
RN2703 = SMD-ARES4H18: tolerance: 66.47236.04L
RN5702 = SMD-ARES4H18: tolerance: 66.22236.A4L
RN6120 = SMD-ARES4H18: tolerance: 66.47336.04L
RT2401 RT2402 = NTC-402H22-U: tolerance: 69.60011.121
SATA1 = C166KK-12209-L: tolerance: 022.10019.0021
SPK1 = 87212-0044N-W01: tolerance: 020.F1076.0004
TP602-TP605 TP607-TP609 TP619 TP808 TP1611 TP1702 TP2111 TP9901 TP9902 TP9904-TP9910 = TPAD28: tolerance: ZZ.PAD28.XXX
TP4402 = TPAD14-OP: tolerance: ZZ.PAD14.001
TSMT1 = QFN48J6-G4D55H40: tolerance: 071.02136.0003
U2401 = SOIC8H69: tolerance: 72.02510.001
U2501 = SOIC8-1H86: tolerance: 072.25128.0D61
U2504 = SKT-SOIC8-1H211: tolerance: 62.10076.031
U2601 = SOIC8H69: tolerance: 74.05606.A71
U2701 = QFN48J6-G465H40: tolerance: 071.00256.0003
U3101 U3102 = SOT-6-1H58: tolerance: 075.00199.007C
U3103 U3401 U3402 U3503 U3504 U5504 = SOT-23-5H40: tolerance: 074.09742.0A9F
U3301 = QFN24-G2D5H40-U: tolerance: 71.05176.003
U4003 = SON14J3020-G2610H34: tolerance: 074.22976.0091
U4007 U4010-U4012 U5301 = DFN8F3-G2517H32: tolerance: 074.05027.0B93
U4009 = SC70-5H44: tolerance: 073.7SZ08.000G
U4013 = SC70-5H44: tolerance: 73.01G07.0HG
U4020 = SC70-5H44: tolerance: 73.01G08.DHH
U4303 = SC70-6H44: tolerance: 74.00199.B7P
U5501 = QFN20-G2D1H34: tolerance: 074.00554.0A73
U5602 = SOIC8H69: tolerance: 72.24C64.K01
USB3R1 USB3R2 = SKT-USB11-138166: tolerance: 022.10005.0F41
USB3R3 USB3R4 = SKT-USB11-160090-3-U: tolerance: 022.10005.0ZQ1
X1801 = SMD49-12H34: tolerance: 082.30003.0301
X1802 = OSC-3225-4P-4H36: tolerance: 082.30040.0171
X3101 = SMD-OSC38H32: tolerance: 082.30005.0A81
XF3101 = XFORM24C1510H168: tolerance: 68.IH601.301

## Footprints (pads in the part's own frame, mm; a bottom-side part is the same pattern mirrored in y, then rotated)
0R0402-PAD
  custom 0.14x0.14 smd: 1(0,0.445) 2(0,-0.445)
0R0402-PAD-1
  custom 0.14x0.14 smd: 1(0,0.445) 2(0,-0.445)
0R0603-PAD-1-U
  custom 0.216x0.216 smd: 1(0,0.762) 2(0,-0.762)
0R0603-PAD-U
  custom 0.216x0.216 smd: 1(0,0.762) 2(0,-0.762)
0R0805-PAD-1-U
  rect 1.397x1.562 smd: 1(0,0.965)
  rect 1.397x1.569 smd: 2(0,-0.965)
0R1206-PAD-1
  rect 1.651x2.057 smd: 1(0,1.397) 2(0,-1.397)
2DC3012-005111F
  round 0.254 hole 1.372 unplated: (-4.5,-4.25) (4.5,4.25)
  oval 1.626x3.226 hole 0.914x2.515: 1(-4.4,2) 2(-2,-2.6)
  oval 3.226x1.626 hole 2.515x0.914: 3(1,4)
23-01122-2A03-B
  rect 0.813x3.988 smd: 1(-4.445,13.3) 2(-3.175,13.3) 3(-1.905,13.3) 4(-0.635,13.3) 5(0.635,13.3) 6(1.905,13.3) 7(3.175,13.3) 8(4.445,13.3)
  round 1.321 hole 0.914: 9(-6.645,0) 10(-4.355,0) 11(4.355,0) 12(6.645,0)
  rect 8.992x3.404 smd: 13(0,-3.5)
40-42087-00211RHF-WH-U1
  round 0.254 hole 1.067 unplated: (-7.5,0)
  round 0.254 hole 1.372 unplated: (0,0)
  rect 3.048x3.404 smd: 1(6.225,0)
  rect 4.496x2.388 smd: 2(-14.95,0)
156-5001902601
  round 0.254 hole 1.702 unplated: (-12.65,0) (12.65,0)
  rect 0.991x2.54 smd: 1(-7.57,8.245) 2(-5.07,8.245) 3(-2.57,8.245) 4(-0.07,8.245) 5(2.43,8.245) 6(4.93,8.245) 7(7.43,8.245) 8(9.055,8.245) 9(-10.07,8.245) 10(10.875,8.245) 11(-11.755,8.245)
  rect 2.057x2.489 smd: 12(-15.225,-8.35) 13(15.225,-8.35)
3801-Q03S-01R
  rect 0.813x1.651 smd: 1(1.25,-2.926) 2(0,-2.926) 3(-1.25,-2.926)
  rect 2.108x2.997 smd: 4(3.796,0) 5(-3.796,0)
50228-0147N-W01
  rect 0.406x1.549 smd: 1(6.5,2.525) 2(5.5,2.525) 3(4.5,2.525) 4(3.5,2.525) 5(2.5,2.525) 6(1.5,2.525) 7(0.5,2.525) 8(-0.5,2.525) 9(-1.5,2.525) 10(-2.5,2.525) 11(-3.5,2.525) 12(-4.5,2.525) 13(-5.5,2.525) 14(-6.5,2.525)
  rect 1.194x1.803 smd: 15(7.797,0) 16(-7.797,0)
50524-0300N-001
  rect 0.305x1.295 smd: 1(-14.5,5.65) 2(-13.5,5.65) 3(-12.5,5.65) 4(-11.5,5.65) 5(-10.5,5.65) 6(-9.5,5.65) 7(-8.5,5.65) 8(-7.5,5.65) 9(-6.5,5.65) 10(-5.5,5.65) 11(-4.5,5.65) 12(-3.5,5.65) 13(-2.5,5.65) 14(-1.5,5.65) 15(-0.5,5.65) 16(0.5,5.65) 17(1.5,5.65) 18(2.5,5.65) 19(3.5,5.65) 20(4.5,5.65) 21(5.5,5.65) 22(6.5,5.65) 23(7.5,5.65) 24(8.5,5.65) 25(9.5,5.65) 26(10.5,5.65) 27(11.5,5.65) 28(12.5,5.65) 29(13.5,5.65) 30(14.5,5.65)
  rect 1.803x2.21 smd: 31(-17.15,0) 32(17.15,0)
51290-0084N-W01
  rect 0.61x1.549 smd: 1(3.5,2.525) 2(2.5,2.525) 3(1.5,2.525) 4(0.5,2.525) 5(-0.5,2.525) 6(-1.5,2.525) 7(-2.5,2.525) 8(-3.5,2.525)
  rect 1.194x1.803 smd: 9(4.8,0) 10(-4.8,0)
51290-0124N-W01
  rect 0.61x1.549 smd: 1(5.5,-2.525) 2(4.5,-2.525) 3(3.5,-2.525) 4(2.5,-2.525) 5(1.5,-2.525) 6(0.5,-2.525) 7(-0.5,-2.525) 8(-1.5,-2.525) 9(-2.5,-2.525) 10(-3.5,-2.525) 11(-4.5,-2.525) 12(-5.5,-2.525)
  rect 1.194x1.803 smd: 13(6.8,0) 14(-6.8,0)
87212-0044N-W01
  rect 0.61x1.549 smd: 1(1.5,2.525) 2(0.5,2.525) 3(-0.5,2.525) 4(-1.5,2.525)
  rect 1.194x1.803 smd: 5(-2.8,0) 6(2.8,0)
APCI0096-P003A
  round 0.254 hole 1.118 unplated: (-10,0)
  round 0.254 hole 1.6 unplated: (10,0)
  rect 0.305x1.549 smd: 1(-9.25,4.725) 2(-9,-1.725) 3(-8.75,4.725) 4(-8.5,-1.725) 5(-8.25,4.725) 6(-8,-1.725) 7(-7.75,4.725) 8(-7.5,-1.725) 9(-7.25,4.725) 10(-7,-1.725) 11(-6.75,4.725) 12(-6.5,-1.725) 13(-6.25,4.725) 14(-6,-1.725) 15(-5.75,4.725) 16(-5.5,-1.725) 17(-5.25,4.725) 18(-5,-1.725) 19(-4.75,4.725) 20(-4.5,-1.725) 21(-4.25,4.725) 22(-4,-1.725) 23(-3.75,4.725) 24(-3.5,-1.725) 25(-3.25,4.725) 26(-3,-1.725) 27(-2.75,4.725) 28(-2.5,-1.725) 29(-2.25,4.725) 30(-2,-1.725) 31(-1.75,4.725) 32(-1.5,-1.725) 33(-1.25,4.725) 34(-1,-1.725) 35(-0.75,4.725) 36(-0.5,-1.725) 37(-0.25,4.725) 38(0,-1.725) 39(0.25,4.725) 40(0.5,-1.725) 41(0.75,4.725) 42(1,-1.725) 43(1.25,4.725) 44(1.5,-1.725) 45(1.75,4.725) 46(2,-1.725) 47(2.25,4.725) 48(2.5,-1.725) 49(2.75,4.725) 50(3,-1.725) 51(3.25,4.725) 52(3.5,-1.725) 53(3.75,4.725) 54(4,-1.725) 55(4.25,4.725) 56(4.5,-1.725) 57(4.75,4.725) 58(5,-1.725) 67(7.25,4.725) 68(7.5,-1.725) 69(7.75,4.725) 70(8,-1.725) 71(8.25,4.725) 72(8.5,-1.725) 73(8.75,4.725) 74(9,-1.725) 75(9.25,4.725)
  rect 1.194x2.743 smd: 76(-10.35,4.5) 77(10.35,4.5)
ARES2H16
  rect 0.356x0.66 smd: 1(-0.325,-0.599) 2(0.325,-0.599) 3(0.325,0.599) 4(-0.325,0.599)
ARES2H18
  rect 0.356x0.66 smd: 1(-0.325,-0.599) 2(0.325,-0.599) 3(0.325,0.599) 4(-0.325,0.599)
ARES8-CN24-UH20
  rect 0.61x0.66 smd: 1(-0.9,-0.486) 4(0.9,-0.486) 5(0.9,0.486) 8(-0.9,0.486)
  rect 0.305x0.66 smd: 2(-0.25,-0.486) 3(0.25,-0.486) 6(0.25,0.486) 7(-0.25,0.486)
AS0BC21-S40BE-7H
  round 0.254 hole 1.168 unplated: (-10,0)
  round 0.254 hole 1.651 unplated: (10,0)
  rect 0.305x1.549 smd: 1(-9.25,5.275) 2(-9,-2.275) 3(-8.75,5.275) 4(-8.5,-2.275) 5(-8.25,5.275) 6(-8,-2.275) 7(-7.75,5.275) 8(-7.5,-2.275) 9(-7.25,5.275) 10(-7,-2.275) 11(-6.75,5.275) 12(-6.5,-2.275) 13(-6.25,5.275) 14(-6,-2.275) 15(-5.75,5.275) 16(-5.5,-2.275) 17(-5.25,5.275) 18(-5,-2.275) 19(-4.75,5.275) 20(-4.5,-2.275) 21(-4.25,5.275) 22(-4,-2.275) 23(-3.75,5.275) 32(-1.5,-2.275) 33(-1.25,5.275) 34(-1,-2.275) 35(-0.75,5.275) 36(-0.5,-2.275) 37(-0.25,5.275) 38(0,-2.275) 39(0.25,5.275) 40(0.5,-2.275) 41(0.75,5.275) 42(1,-2.275) 43(1.25,5.275) 44(1.5,-2.275) 45(1.75,5.275) 46(2,-2.275) 47(2.25,5.275) 48(2.5,-2.275) 49(2.75,5.275) 50(3,-2.275) 51(3.25,5.275) 52(3.5,-2.275) 53(3.75,5.275) 54(4,-2.275) 55(4.25,5.275) 56(4.5,-2.275) 57(4.75,5.275) 58(5,-2.275) 59(5.25,5.275) 60(5.5,-2.275) 61(5.75,5.275) 62(6,-2.275) 63(6.25,5.275) 64(6.5,-2.275) 65(6.75,5.275) 66(7,-2.275) 67(7.25,5.275) 68(7.5,-2.275) 69(7.75,5.275) 70(8,-2.275) 71(8.25,5.275) 72(8.5,-2.275) 73(8.75,5.275) 74(9,-2.275) 75(9.25,5.275)
  rect 1.194x2.743 smd: 76(-10.35,4.5) 77(10.35,4.5)
ASAA821-E8RB0-7H
  round 0.254 hole 1.6 unplated: (-34.4,0)
  round 0.254 hole 1.118 unplated: (34.4,0)
  custom 0.089x0.089 smd: 1(-33.375,-4.1) 2(-33.125,4.1) 3(-32.875,-4.1) 4(-32.625,4.1) 5(-32.375,-4.1) 6(-32.125,4.1) 7(-31.875,-4.1) 8(-31.625,4.1) 9(-31.375,-4.1) 10(-31.125,4.1) 11(-30.875,-4.1) 12(-30.625,4.1) 13(-30.375,-4.1) 14(-30.125,4.1) 15(-29.875,-4.1) 16(-29.625,4.1) 17(-29.375,-4.1) 18(-29.125,4.1) 19(-28.875,-4.1) 20(-28.625,4.1) 21(-28.375,-4.1) 22(-28.125,4.1) 23(-27.875,-4.1) 24(-27.625,4.1) 25(-27.375,-4.1) 26(-27.125,4.1) 27(-26.875,-4.1) 28(-26.625,4.1) 29(-26.375,-4.1) 30(-26.125,4.1) 31(-25.875,-4.1) 32(-25.625,4.1) 33(-25.375,-4.1) 34(-25.125,4.1) 35(-24.875,-4.1) 36(-24.625,4.1) 37(-24.375,-4.1) 38(-24.125,4.1) 39(-23.875,-4.1) 40(-23.625,4.1) 41(-23.375,-4.1) 42(-23.125,4.1) 43(-22.875,-4.1) 44(-22.625,4.1) 45(-22.375,-4.1) 46(-22.125,4.1) 47(-21.875,-4.1) 48(-21.625,4.1) 49(-21.375,-4.1) 50(-21.125,4.1) 51(-20.875,-4.1) 52(-20.625,4.1) 53(-20.375,-4.1) 54(-20.125,4.1) 55(-19.875,-4.1) 56(-19.625,4.1) 57(-19.375,-4.1) 58(-19.125,4.1) 59(-18.875,-4.1) 60(-18.625,4.1) 61(-18.375,-4.1) 62(-18.125,4.1) 63(-17.875,-4.1) 64(-17.625,4.1) 65(-17.375,-4.1) 66(-17.125,4.1) 67(-16.875,-4.1) 68(-16.625,4.1) 69(-16.375,-4.1) 70(-16.125,4.1) 71(-15.875,-4.1) 72(-15.625,4.1) 73(-15.375,-4.1) 74(-15.125,4.1) 75(-14.875,-4.1) 76(-14.625,4.1) 77(-14.375,-4.1) 78(-14.125,4.1) 79(-13.875,-4.1) 80(-13.625,4.1) 81(-13.375,-4.1) 82(-13.125,4.1) 83(-12.875,-4.1) 84(-12.625,4.1) 85(-12.375,-4.1) 86(-12.125,4.1) 87(-11.875,-4.1) 88(-11.625,4.1) 89(-11.375,-4.1) 90(-11.125,4.1) 91(-10.875,-4.1) 92(-10.625,4.1) 93(-10.375,-4.1) 94(-10.125,4.1) 95(-9.875,-4.1) 96(-9.625,4.1) 97(-9.375,-4.1) 98(-9.125,4.1) 99(-8.875,-4.1) 100(-8.625,4.1) 101(-8.375,-4.1) 102(-8.125,4.1) 103(-7.875,-4.1) 104(-7.625,4.1) 105(-7.375,-4.1) 106(-7.125,4.1) 107(-6.875,-4.1) 108(-6.625,4.1) 109(-6.375,-4.1) 110(-6.125,4.1) 111(-5.875,-4.1) 112(-5.625,4.1) 113(-5.375,-4.1) 114(-5.125,4.1) 115(-4.875,-4.1) 116(-4.625,4.1) 117(-4.375,-4.1) 118(-4.125,4.1) 119(-3.875,-4.1) 120(-3.625,4.1) 121(-3.375,-4.1) 122(-3.125,4.1) 123(-2.875,-4.1) 124(-2.625,4.1) 125(-2.375,-4.1) 126(-2.125,4.1) 127(-1.875,-4.1) 128(-1.625,4.1) 129(-1.375,-4.1) 130(-1.125,4.1) 131(-0.875,-4.1) 132(-0.625,4.1) 133(-0.375,-4.1) 134(-0.125,4.1) 135(0.125,-4.1) 136(0.375,4.1) 137(0.625,-4.1) 138(0.875,4.1) 139(1.125,-4.1) 140(1.375,4.1) 141(1.625,-4.1) 142(1.875,4.1) 143(2.125,-4.1) 144(2.375,4.1) 145(4.625,-4.1) 146(4.875,4.1) 147(5.125,-4.1) 148(5.375,4.1) 149(5.625,-4.1) 150(5.875,4.1) 151(6.125,-4.1) 152(6.375,4.1) 153(6.625,-4.1) 154(6.875,4.1) 155(7.125,-4.1) 156(7.375,4.1) 157(7.625,-4.1) 158(7.875,4.1) 159(8.125,-4.1) 160(8.375,4.1) 161(8.625,-4.1) 162(8.875,4.1) 163(9.125,-4.1) 164(9.375,4.1) 165(9.625,-4.1) 166(9.875,4.1) 167(10.125,-4.1) 168(10.375,4.1) 169(10.625,-4.1) 170(10.875,4.1) 171(11.125,-4.1) 172(11.375,4.1) 173(11.625,-4.1) 174(11.875,4.1) 175(12.125,-4.1) 176(12.375,4.1) 177(12.625,-4.1) 178(12.875,4.1) 179(13.125,-4.1) 180(13.375,4.1) 181(13.625,-4.1) 182(13.875,4.1) 183(14.125,-4.1) 184(14.375,4.1) 185(14.625,-4.1) 186(14.875,4.1) 187(15.125,-4.1) 188(15.375,4.1) 189(15.625,-4.1) 190(15.875,4.1) 191(16.125,-4.1) 192(16.375,4.1) 193(16.625,-4.1) 194(16.875,4.1) 195(17.125,-4.1) 196(17.375,4.1) 197(17.625,-4.1) 198(17.875,4.1) 199(18.125,-4.1) 200(18.375,4.1) 201(18.625,-4.1) 202(18.875,4.1) 203(19.125,-4.1) 204(19.375,4.1) 205(19.625,-4.1) 206(19.875,4.1) 207(20.125,-4.1) 208(20.375,4.1) 209(20.625,-4.1) 210(20.875,4.1) 211(21.125,-4.1) 212(21.375,4.1) 213(21.625,-4.1) 214(21.875,4.1) 215(22.125,-4.1) 216(22.375,4.1) 217(22.625,-4.1) 218(22.875,4.1) 219(23.125,-4.1) 220(23.375,4.1) 221(23.625,-4.1) 222(23.875,4.1) 223(24.125,-4.1) 224(24.375,4.1) 225(24.625,-4.1) 226(24.875,4.1) 227(25.125,-4.1) 228(25.375,4.1) 229(25.625,-4.1) 230(25.875,4.1) 231(26.125,-4.1) 232(26.375,4.1) 233(26.625,-4.1) 234(26.875,4.1) 235(27.125,-4.1) 236(27.375,4.1) 237(27.625,-4.1) 238(27.875,4.1) 239(28.125,-4.1) 240(28.375,4.1) 241(28.625,-4.1) 242(28.875,4.1) 243(29.125,-4.1) 244(29.375,4.1) 245(29.625,-4.1) 246(29.875,4.1) 247(30.125,-4.1) 248(30.375,4.1) 249(30.625,-4.1) 250(30.875,4.1) 251(31.125,-4.1) 252(31.375,4.1) 253(31.625,-4.1) 254(31.875,4.1) 255(32.125,-4.1) 256(32.375,4.1) 257(32.625,-4.1) 258(32.875,4.1) 259(33.125,-4.1) 260(33.375,4.1)
  rect 2.007x3.505 smd: 261(37.75,-12) 262(-37.75,-8)
ASAA821-H4RB5-7H
  round 0.254 hole 1.6 unplated: (-34.4,0)
  round 0.254 hole 1.118 unplated: (34.4,0)
  custom 0.089x0.089 smd: 1(-33.375,-4.1) 2(-33.125,4.1) 3(-32.875,-4.1) 4(-32.625,4.1) 5(-32.375,-4.1) 6(-32.125,4.1) 7(-31.875,-4.1) 8(-31.625,4.1) 9(-31.375,-4.1) 10(-31.125,4.1) 11(-30.875,-4.1) 12(-30.625,4.1) 13(-30.375,-4.1) 14(-30.125,4.1) 15(-29.875,-4.1) 16(-29.625,4.1) 17(-29.375,-4.1) 18(-29.125,4.1) 19(-28.875,-4.1) 20(-28.625,4.1) 21(-28.375,-4.1) 22(-28.125,4.1) 23(-27.875,-4.1) 24(-27.625,4.1) 25(-27.375,-4.1) 26(-27.125,4.1) 27(-26.875,-4.1) 28(-26.625,4.1) 29(-26.375,-4.1) 30(-26.125,4.1) 31(-25.875,-4.1) 32(-25.625,4.1) 33(-25.375,-4.1) 34(-25.125,4.1) 35(-24.875,-4.1) 36(-24.625,4.1) 37(-24.375,-4.1) 38(-24.125,4.1) 39(-23.875,-4.1) 40(-23.625,4.1) 41(-23.375,-4.1) 42(-23.125,4.1) 43(-22.875,-4.1) 44(-22.625,4.1) 45(-22.375,-4.1) 46(-22.125,4.1) 47(-21.875,-4.1) 48(-21.625,4.1) 49(-21.375,-4.1) 50(-21.125,4.1) 51(-20.875,-4.1) 52(-20.625,4.1) 53(-20.375,-4.1) 54(-20.125,4.1) 55(-19.875,-4.1) 56(-19.625,4.1) 57(-19.375,-4.1) 58(-19.125,4.1) 59(-18.875,-4.1) 60(-18.625,4.1) 61(-18.375,-4.1) 62(-18.125,4.1) 63(-17.875,-4.1) 64(-17.625,4.1) 65(-17.375,-4.1) 66(-17.125,4.1) 67(-16.875,-4.1) 68(-16.625,4.1) 69(-16.375,-4.1) 70(-16.125,4.1) 71(-15.875,-4.1) 72(-15.625,4.1) 73(-15.375,-4.1) 74(-15.125,4.1) 75(-14.875,-4.1) 76(-14.625,4.1) 77(-14.375,-4.1) 78(-14.125,4.1) 79(-13.875,-4.1) 80(-13.625,4.1) 81(-13.375,-4.1) 82(-13.125,4.1) 83(-12.875,-4.1) 84(-12.625,4.1) 85(-12.375,-4.1) 86(-12.125,4.1) 87(-11.875,-4.1) 88(-11.625,4.1) 89(-11.375,-4.1) 90(-11.125,4.1) 91(-10.875,-4.1) 92(-10.625,4.1) 93(-10.375,-4.1) 94(-10.125,4.1) 95(-9.875,-4.1) 96(-9.625,4.1) 97(-9.375,-4.1) 98(-9.125,4.1) 99(-8.875,-4.1) 100(-8.625,4.1) 101(-8.375,-4.1) 102(-8.125,4.1) 103(-7.875,-4.1) 104(-7.625,4.1) 105(-7.375,-4.1) 106(-7.125,4.1) 107(-6.875,-4.1) 108(-6.625,4.1) 109(-6.375,-4.1) 110(-6.125,4.1) 111(-5.875,-4.1) 112(-5.625,4.1) 113(-5.375,-4.1) 114(-5.125,4.1) 115(-4.875,-4.1) 116(-4.625,4.1) 117(-4.375,-4.1) 118(-4.125,4.1) 119(-3.875,-4.1) 120(-3.625,4.1) 121(-3.375,-4.1) 122(-3.125,4.1) 123(-2.875,-4.1) 124(-2.625,4.1) 125(-2.375,-4.1) 126(-2.125,4.1) 127(-1.875,-4.1) 128(-1.625,4.1) 129(-1.375,-4.1) 130(-1.125,4.1) 131(-0.875,-4.1) 132(-0.625,4.1) 133(-0.375,-4.1) 134(-0.125,4.1) 135(0.125,-4.1) 136(0.375,4.1) 137(0.625,-4.1) 138(0.875,4.1) 139(1.125,-4.1) 140(1.375,4.1) 141(1.625,-4.1) 142(1.875,4.1) 143(2.125,-4.1) 144(2.375,4.1) 145(4.625,-4.1) 146(4.875,4.1) 147(5.125,-4.1) 148(5.375,4.1) 149(5.625,-4.1) 150(5.875,4.1) 151(6.125,-4.1) 152(6.375,4.1) 153(6.625,-4.1) 154(6.875,4.1) 155(7.125,-4.1) 156(7.375,4.1) 157(7.625,-4.1) 158(7.875,4.1) 159(8.125,-4.1) 160(8.375,4.1) 161(8.625,-4.1) 162(8.875,4.1) 163(9.125,-4.1) 164(9.375,4.1) 165(9.625,-4.1) 166(9.875,4.1) 167(10.125,-4.1) 168(10.375,4.1) 169(10.625,-4.1) 170(10.875,4.1) 171(11.125,-4.1) 172(11.375,4.1) 173(11.625,-4.1) 174(11.875,4.1) 175(12.125,-4.1) 176(12.375,4.1) 177(12.625,-4.1) 178(12.875,4.1) 179(13.125,-4.1) 180(13.375,4.1) 181(13.625,-4.1) 182(13.875,4.1) 183(14.125,-4.1) 184(14.375,4.1) 185(14.625,-4.1) 186(14.875,4.1) 187(15.125,-4.1) 188(15.375,4.1) 189(15.625,-4.1) 190(15.875,4.1) 191(16.125,-4.1) 192(16.375,4.1) 193(16.625,-4.1) 194(16.875,4.1) 195(17.125,-4.1) 196(17.375,4.1) 197(17.625,-4.1) 198(17.875,4.1) 199(18.125,-4.1) 200(18.375,4.1) 201(18.625,-4.1) 202(18.875,4.1) 203(19.125,-4.1) 204(19.375,4.1) 205(19.625,-4.1) 206(19.875,4.1) 207(20.125,-4.1) 208(20.375,4.1) 209(20.625,-4.1) 210(20.875,4.1) 211(21.125,-4.1) 212(21.375,4.1) 213(21.625,-4.1) 214(21.875,4.1) 215(22.125,-4.1) 216(22.375,4.1) 217(22.625,-4.1) 218(22.875,4.1) 219(23.125,-4.1) 220(23.375,4.1) 221(23.625,-4.1) 222(23.875,4.1) 223(24.125,-4.1) 224(24.375,4.1) 225(24.625,-4.1) 226(24.875,4.1) 227(25.125,-4.1) 228(25.375,4.1) 229(25.625,-4.1) 230(25.875,4.1) 231(26.125,-4.1) 232(26.375,4.1) 233(26.625,-4.1) 234(26.875,4.1) 235(27.125,-4.1) 236(27.375,4.1) 237(27.625,-4.1) 238(27.875,4.1) 239(28.125,-4.1) 240(28.375,4.1) 241(28.625,-4.1) 242(28.875,4.1) 243(29.125,-4.1) 244(29.375,4.1) 245(29.625,-4.1) 246(29.875,4.1) 247(30.125,-4.1) 248(30.375,4.1) 249(30.625,-4.1) 250(30.875,4.1) 251(31.125,-4.1) 252(31.375,4.1) 253(31.625,-4.1) 254(31.875,4.1) 255(32.125,-4.1) 256(32.375,4.1) 257(32.625,-4.1) 258(32.875,4.1) 259(33.125,-4.1) 260(33.375,4.1)
  rect 3.505x4.597 smd: 261(-33.8,-12) 262(33.8,-12)
BGA1526M2550-1H51
  round 0.356 smd: A3(10.767,-24.365) A48(-11.405,-24.365) A49(-11.865,-23.905) B2(11.309,-23.816) C1(11.865,-23.255) DW1(11.865,23.905) DW2(11.405,24.365) DW48(-11.405,24.365) DW49(-11.865,23.905)
  round 0.33 smd: A4(10.117,-24.365) A47(-10.755,-24.365) B3(10.666,-23.723) B48(-11.237,-23.737) C2(11.22,-23.172) C49(-11.865,-23.255) D1(11.865,-22.605) DE12(6.31,17.032) DE13(5.48,17.032) DE15(4.65,17.032) DE17(3.82,17.032) DE18(2.99,17.032) DE20(2.16,17.032) DE22(1.33,17.032) DE23(0.5,17.032) DE26(-0.33,17.032) DE28(-1.16,17.032) DE29(-1.99,17.032) DE31(-2.82,17.032) DE33(-3.65,17.032) DF12(6.31,17.682) DF13(5.48,17.682) DF15(4.65,17.682) DF17(3.82,17.682) DF18(2.99,17.682) DF20(2.16,17.682) DF22(1.33,17.682) DF23(0.5,17.682) DF26(-0.33,17.682) DF28(-1.16,17.682) DF29(-1.99,17.682) DF31(-2.82,17.682) DF33(-3.65,17.682) DG12(6.31,18.332) DG13(5.48,18.332) DG15(4.65,18.332) DG17(3.82,18.332) DG18(2.99,18.332) DG20(2.16,18.332) DG22(1.33,18.332) DG23(0.5,18.332) DG26(-0.33,18.332) DG28(-1.16,18.332) DG29(-1.99,18.332) DG31(-2.82,18.332) DG33(-3.65,18.332) DU1(11.865,23.255) DU49(-11.865,23.255) DV2(11.237,23.737) DV48(-11.237,23.737) DW3(10.755,24.365) DW47(-10.755,24.365)
  round 0.305 smd: A5(9.467,-24.365) A7(8.658,-24.365) A33(-3.593,-24.365) A43(-8.707,-24.365) A44(-9.455,-24.365) A46(-10.105,-24.365) AA12(6.127,-14.312) AA35(-4.855,-14.311) AA37(-5.778,-14.311) AA45(-9.59,-14.246) AA47(-10.861,-14.246) AB3(10.893,-13.923) AB5(9.905,-13.923) AB6(9.189,-13.855) AB7(8.539,-13.855) AB9(7.889,-13.855) AB10(7.239,-13.855) AB11(6.589,-13.855) AB13(5.665,-13.855) AB34(-4.393,-13.853) AB36(-5.316,-13.853) AB38(-6.24,-13.853) AB39(-6.89,-13.853) AB41(-7.54,-13.853) AB42(-8.19,-13.853) AB43(-8.84,-13.853) AB45(-9.915,-13.626) AB47(-10.565,-13.626) AC3(10.565,-13.249) AC5(9.915,-13.249) AC12(6.127,-13.397) AC35(-4.855,-13.396) AC37(-5.778,-13.396) AC45(-9.59,-12.995) AC46(-10.241,-12.995) AD3(10.89,-12.686) AD4(10.24,-12.686) AD6(9.189,-12.94) AD7(8.539,-12.94) AD9(7.889,-12.94) AD10(7.239,-12.94) AD11(6.589,-12.94) AD34(-4.393,-12.938) AD35(-4.855,-12.481) AD36(-5.316,-12.938) AD37(-5.778,-12.481) AD38(-6.24,-12.938) AD39(-6.89,-12.938) AD41(-7.54,-12.938) AD42(-8.19,-12.938) AD43(-8.84,-12.938) AE3(10.565,-12.123) AE5(9.915,-12.123) AE6(9.189,-12.025) AE7(8.539,-12.025) AE9(7.889,-12.025) AE11(6.965,-12.025) AE36(-5.316,-12.023) AE38(-6.24,-12.023) AE39(-6.89,-12.023) AE41(-7.54,-12.023) AE42(-8.19,-12.023) AE43(-8.84,-12.023) AE45(-9.915,-12.364) AE47(-10.565,-12.364) AF10(7.427,-11.567) AF37(-5.778,-11.566) AF45(-9.59,-11.744) AF47(-10.861,-11.744) AG3(10.893,-11.449) AG5(9.905,-11.449) AG6(9.189,-11.11) AG7(8.539,-11.11) AG9(7.889,-11.11) AG11(6.965,-11.11) AG36(-5.316,-11.108) AG38(-6.24,-11.108) AG39(-6.89,-11.108) AG41(-7.54,-11.108) AG42(-8.19,-11.108) AG43(-8.84,-11.108) AG45(-9.915,-11.124) AG47(-10.565,-11.124) AH10(7.427,-10.652) AH37(-5.778,-10.651) AH45(-9.59,-10.493) AH46(-10.241,-10.493) AJ3(10.489,-10.195) AJ5(9.839,-10.195) AJ6(9.189,-10.195) AJ7(8.539,-10.195) AJ9(7.889,-10.195) AJ11(6.965,-10.195) AJ36(-5.316,-10.193) AJ38(-6.24,-10.193) AJ39(-6.89,-10.193) AJ41(-7.54,-10.193) AJ42(-8.19,-10.193) AJ43(-8.84,-10.193) AK10(7.427,-9.737) AK37(-5.778,-9.736) AK45(-9.915,-9.862) AK47(-10.565,-9.862) AL3(10.489,-9.28) AL5(9.839,-9.28) AL6(9.189,-9.28) AL7(8.539,-9.28) AL9(7.889,-9.28) AL11(6.965,-9.28) AL36(-5.316,-9.278) AL38(-6.24,-9.278) AL39(-6.89,-9.278) AL41(-7.54,-9.278) AL42(-8.19,-9.278) AL43(-8.84,-9.278) AL45(-9.59,-9.242) AL47(-10.861,-9.242) AM10(7.427,-8.822) AM37(-5.778,-8.821) AM45(-9.915,-8.622) AM47(-10.565,-8.622) AN3(10.489,-8.365) AN5(9.839,-8.365) AN6(9.189,-8.365) AN7(8.539,-8.365) AN9(7.889,-8.365) AN11(6.965,-8.365) AN36(-5.316,-8.363) AN38(-6.24,-8.363) AN39(-6.89,-8.363) AN41(-7.54,-8.363) AN42(-8.19,-8.363) AN43(-8.84,-8.363) AN45(-9.59,-7.991) AN46(-10.241,-7.991) AP10(7.427,-7.907) AP37(-5.778,-7.906) AR3(10.489,-7.45) AR5(9.839,-7.45) AR6(9.189,-7.45) AR7(8.539,-7.45) AR9(7.889,-7.45) AR10(7.427,-6.992) AR11(6.965,-7.45) AR36(-5.316,-7.448) AR37(-5.778,-6.991) AR38(-6.24,-7.448) AR39(-6.89,-7.448) AR41(-7.54,-7.448) AR42(-8.19,-7.448) AR43(-8.84,-7.448) AR45(-9.915,-7.36) AR47(-10.565,-7.36) AT3(10.489,-6.535) AT5(9.839,-6.535) AT6(9.189,-6.535) AT7(8.539,-6.535) AT9(7.889,-6.535) AT11(6.965,-6.535) AT36(-5.316,-6.533) AT38(-6.24,-6.533) AT39(-6.89,-6.533) AT41(-7.54,-6.533) AT42(-8.19,-6.533) AT43(-8.84,-6.533) AT45(-9.59,-6.74) AT47(-10.861,-6.74) AU10(7.427,-6.077) AU37(-5.778,-6.076) AU45(-9.915,-6.12) AU47(-10.565,-6.12) AV3(10.489,-5.62) AV5(9.839,-5.62) AV6(9.189,-5.62) AV7(8.539,-5.62) AV9(7.889,-5.62) AV11(6.965,-5.62) AV36(-5.316,-5.618) AV38(-6.24,-5.618) AV39(-6.89,-5.618) AV41(-7.54,-5.618) AV42(-8.19,-5.618) AV43(-8.84,-5.618) AV45(-9.59,-5.489) AV46(-10.241,-5.489) AW10(7.427,-5.162) AW37(-5.778,-5.161) AY3(10.489,-4.705) AY5(9.839,-4.705) AY6(9.189,-4.705) AY7(8.539,-4.705) AY9(7.889,-4.705) AY11(6.965,-4.705) AY36(-5.316,-4.703) AY38(-6.24,-4.703) AY39(-6.89,-4.703) AY41(-7.54,-4.703) AY42(-8.19,-4.703) AY43(-8.84,-4.703) AY45(-9.915,-4.858) AY47(-10.565,-4.858) B4(10.016,-23.723) B7(8.658,-23.715) B33(-3.593,-23.715) B43(-8.707,-23.715) B45(-9.956,-23.577) B47(-10.587,-23.737) BA10(7.427,-4.247) BA37(-5.778,-4.246) BA45(-9.59,-4.238) BA47(-10.861,-4.238) BB3(10.489,-3.79) BB5(9.839,-3.79) BB6(9.189,-3.79) BB7(8.539,-3.79) BB9(7.889,-3.79) BB11(6.965,-3.79) BB36(-5.316,-3.788) BB38(-6.24,-3.788) BB39(-6.89,-3.788) BB41(-7.54,-3.788) BB42(-8.19,-3.788) BB43(-8.84,-3.788) BB45(-9.915,-3.618) BB47(-10.565,-3.618) BC10(7.427,-3.332) BC37(-5.778,-3.331) BD3(10.489,-2.875) BD5(9.839,-2.875) BD6(9.189,-2.875) BD7(8.539,-2.875) BD9(7.889,-2.875) BD11(6.965,-2.875) BD36(-5.316,-2.873) BD38(-6.24,-2.873) BD39(-6.89,-2.873) BD41(-7.54,-2.873) BD42(-8.19,-2.873) BD43(-8.84,-2.873) BD45(-9.59,-2.987) BD46(-10.241,-2.987) BE10(7.427,-2.417) BE37(-5.778,-2.416) BE45(-9.915,-2.356) BE47(-10.565,-2.356) BF3(10.489,-1.96) BF5(9.839,-1.96) BF6(9.189,-1.96) BF7(8.539,-1.96) BF9(7.889,-1.96) BF10(7.427,-1.502) BF11(6.965,-1.96) BF36(-5.316,-1.958) BF37(-5.778,-1.501) BF38(-6.24,-1.958) BF39(-6.89,-1.958) BF41(-7.54,-1.958) BF42(-8.19,-1.958) BF43(-8.84,-1.958) BF45(-9.59,-1.736) BF47(-10.861,-1.736) BG3(10.489,-1.045) BG5(9.839,-1.045) BG6(9.189,-1.045) BG7(8.539,-1.045) BG9(7.889,-1.045) BG11(6.965,-1.045) BG36(-5.316,-1.043) BG38(-6.24,-1.043) BG39(-6.89,-1.043) BG41(-7.54,-1.043) BG42(-8.19,-1.043) BG43(-8.84,-1.043) BG45(-9.915,-1.116) BG47(-10.565,-1.116) BH10(7.427,-0.587) BH37(-5.778,-0.586) BJ3(10.489,-0.13) BJ5(9.839,-0.13) BJ6(9.189,-0.13) BJ7(8.539,-0.13) BJ9(7.889,-0.13) BJ11(6.965,-0.13) BJ36(-5.316,-0.128) BJ38(-6.24,-0.128) BJ39(-6.89,-0.128) BJ41(-7.54,-0.128) BJ42(-8.19,-0.128) BJ43(-8.84,-0.128) BJ45(-9.59,-0.485) BJ46(-10.241,-0.485) BL10(7.427,0.328) BL37(-5.778,0.33) BL45(-9.915,0.146) BL47(-10.565,0.146) BM3(10.489,0.786) BM5(9.839,0.786) BM6(9.189,0.786) BM7(8.539,0.786) BM9(7.889,0.786) BM11(6.965,0.786) BM36(-5.316,0.787) BM38(-6.24,0.787) BM39(-6.89,0.787) BM41(-7.54,0.787) BM42(-8.19,0.787) BM43(-8.84,0.787) BM45(-9.59,0.766) BM47(-10.861,0.766) BN10(7.427,1.243) BN37(-5.778,1.245) BN45(-9.915,1.386) BN47(-10.565,1.386) BP3(10.489,1.701) BP5(9.839,1.701) BP6(9.189,1.701) BP7(8.539,1.701) BP9(7.889,1.701) BP11(6.965,1.701) BP36(-5.316,1.702) BP38(-6.24,1.702) BP39(-6.89,1.702) BP41(-7.54,1.702) BP42(-8.19,1.702) BP43(-8.84,1.702) BR10(7.427,2.158) BR37(-5.778,2.16) BR45(-9.59,2.017) BR46(-10.241,2.017) BT3(10.489,2.616) BT5(9.839,2.616) BT6(9.189,2.616) BT7(8.539,2.616) BT9(7.889,2.616) BT11(6.965,2.616) BT36(-5.316,2.617) BT38(-6.24,2.617) BT39(-6.89,2.617) BT41(-7.54,2.617) BT42(-8.19,2.617) BT43(-8.84,2.617) BT45(-9.915,2.648) BT47(-10.565,2.648) BU10(7.427,3.073) BU37(-5.778,3.075) BU45(-9.59,3.268) BU47(-10.861,3.268) BV3(10.489,3.531) BV5(9.839,3.531) BV6(9.189,3.531) BV7(8.539,3.531) BV9(7.889,3.531) BV11(6.965,3.531) BV36(-5.316,3.532) BV38(-6.24,3.532) BV39(-6.89,3.532) BV41(-7.54,3.532) BV42(-8.19,3.532) BV43(-8.84,3.532) BV45(-9.915,3.888) BV47(-10.565,3.888) BW3(10.489,4.446) BW5(9.839,4.446) BW6(9.189,4.446) BW7(8.539,4.446) BW9(7.889,4.446) BW10(7.427,3.988) BW11(6.965,4.446) BW36(-5.316,4.447) BW37(-5.778,3.99) BW38(-6.24,4.447) BW39(-6.89,4.447) BW41(-7.54,4.447) BW42(-8.19,4.447) BW43(-8.84,4.447) BY10(7.427,4.903) BY37(-5.778,4.905) BY45(-9.59,4.519) BY46(-10.241,4.519) C3(10.577,-23.079) C5(9.927,-23.079) C6(9.332,-23.393) C7(8.658,-23.065) C8(8.095,-23.39) C9(7.532,-23.065) C11(6.858,-23.393) C12(6.184,-23.065) C13(5.621,-23.39) C14(5.058,-23.065) C16(4.384,-23.393) C33(-3.593,-23.065) C34(-4.176,-23.361) C35(-4.795,-23.065) C38(-6.077,-23.065) C39(-6.73,-23.361) C40(-7.383,-23.065) C43(-8.707,-23.065) C44(-9.336,-23.359) C47(-10.479,-23.087) C48(-11.234,-23.087) CA3(10.489,5.361) CA5(9.839,5.361) CA6(9.189,5.361) CA7(8.539,5.361) CA9(7.889,5.361) CA11(6.965,5.361) CA36(-5.316,5.362) CA38(-6.24,5.362) CA39(-6.89,5.362) CA41(-7.54,5.362) CA42(-8.19,5.362) CA43(-8.84,5.362) CA45(-9.915,5.15) CA47(-10.565,5.15) CB10(7.427,5.818) CB37(-5.778,5.82) CB45(-9.59,5.77) CB47(-10.861,5.77) CC3(10.893,6.149) CC5(9.905,6.149) CC6(9.189,6.276) CC7(8.539,6.276) CC9(7.889,6.276) CC11(6.965,6.276) CC36(-5.316,6.277) CC38(-6.24,6.277) CC39(-6.89,6.277) CC41(-7.54,6.277) CC42(-8.19,6.277) CC43(-8.84,6.277) CC45(-9.915,6.39) CC47(-10.565,6.39) CD3(10.565,6.823) CD5(9.915,6.823) CD10(7.427,6.733) CE3(10.89,7.386) CE4(10.24,7.386) CE6(9.189,7.191) CE7(8.539,7.191) CE9(7.889,7.191) CE11(6.965,7.191) CE34(-4.29,7.192) CE35(-4.94,7.192) CE37(-5.59,7.192) CE38(-6.24,7.192) CE39(-6.89,7.192) CE41(-7.54,7.192) CE42(-8.19,7.192) CE43(-8.84,7.192) CE45(-9.59,7.021) CE46(-10.241,7.021) CF3(10.565,7.949) CF5(9.915,7.949) CF10(7.427,7.648) CF33(-3.828,7.65) CF45(-9.915,7.652) CF47(-10.565,7.652) CG6(9.189,8.106) CG7(8.539,8.106) CG9(7.889,8.106) CG11(6.965,8.106) CG32(-3.366,8.107) CG34(-4.29,8.107) CG35(-4.94,8.107) CG37(-5.59,8.107) CG38(-6.24,8.107) CG39(-6.89,8.107) CG41(-7.54,8.107) CG42(-8.19,8.107) CG43(-8.84,8.107) CG45(-9.59,8.272) CG47(-10.861,8.272) CH3(10.893,8.623) CH5(9.905,8.623) CH10(7.427,8.563) CH33(-3.828,8.689) CH45(-9.915,8.892) CH47(-10.565,8.892) CJ3(10.565,9.297) CJ5(9.915,9.297) CJ6(9.189,9.021) CJ7(8.539,9.021) CJ9(7.889,9.021) CJ11(6.965,9.021) CJ32(-3.366,9.272) CJ34(-4.29,9.272) CJ35(-4.94,9.272) CJ37(-5.59,9.272) CJ38(-6.24,9.272) CJ39(-6.89,9.272) CJ41(-7.54,9.272) CJ42(-8.19,9.272) CJ43(-8.84,9.272) CK3(10.89,9.86) CK4(10.24,9.86) CK6(9.189,9.936) CK7(8.539,9.936) CK9(7.889,9.936) CK10(7.427,9.478) CK11(6.965,9.936) CK33(-3.828,9.73) CK45(-9.59,9.523) CK46(-10.241,9.523) CL3(10.565,10.423) CL5(9.915,10.423) CL10(7.427,10.393) CL32(-3.366,10.187) CL34(-4.29,10.187) CL35(-4.94,10.187) CL37(-5.59,10.187) CL38(-6.24,10.187) CL39(-6.89,10.187) CL41(-7.54,10.187) CL42(-8.19,10.187) CL43(-8.84,10.187) CL45(-9.915,10.154) CL47(-10.565,10.154) CM6(9.189,10.851) CM7(8.539,10.851) CM9(7.889,10.851) CM11(6.965,10.851) CM33(-3.828,10.645) CM45(-9.59,10.774) CM47(-10.861,10.774) CN3(10.893,11.097) CN5(9.905,11.097) CN10(7.427,11.308) CN32(-3.366,11.102) CN34(-4.29,11.102) CN35(-4.94,11.102) CN37(-5.59,11.102) CN38(-6.24,11.102) CN39(-6.89,11.102) CN41(-7.54,11.102) CN42(-8.19,11.102) CN43(-8.84,11.102) CN45(-9.915,11.394) CN47(-10.565,11.394) CP3(10.565,11.771) CP5(9.915,11.771) CP6(9.189,11.766) CP7(8.539,11.766) CP9(7.889,11.766) CP11(6.965,11.766) CP33(-3.828,11.56) CR3(10.89,12.334) CR4(10.24,12.334) CR10(7.427,12.223) CR32(-3.366,12.017) CR34(-4.29,12.017) CR35(-4.94,12.017) CR37(-5.59,12.017) CR38(-6.24,12.017) CR39(-6.89,12.017) CR41(-7.54,12.017) CR42(-8.19,12.017) CR43(-8.84,12.017) CR45(-9.59,12.025) CR46(-10.241,12.025) CT3(10.565,12.897) CT5(9.915,12.897) CT6(9.189,12.681) CT7(8.539,12.681) CT9(7.889,12.681) CT11(6.965,12.681) CT32(-3.366,12.932) CT33(-3.828,12.475) CT34(-4.29,12.932) CT35(-4.94,12.932) CT37(-5.59,12.932) CT38(-6.24,12.932) CT39(-6.89,12.932) CT41(-7.54,12.932) CT42(-8.19,12.932) CT43(-8.84,12.932) CT45(-9.915,12.656) CT47(-10.565,12.656) CU10(7.427,13.138) CU33(-3.828,13.39) CU45(-9.59,13.276) CU47(-10.861,13.276) CV3(10.893,13.571) CV5(9.905,13.571) CV6(9.189,13.596) CV7(8.539,13.596) CV9(7.889,13.596) CV11(6.965,13.596) CV32(-3.366,13.847) CV34(-4.29,13.847) CV35(-4.94,13.847) CV37(-5.59,13.847) CV38(-6.24,13.847) CV39(-6.89,13.847) CV41(-7.54,13.847) CV42(-8.19,13.847) CV43(-8.84,13.847) CV45(-9.915,13.896) CV47(-10.565,13.896) CW3(10.565,14.245) CW5(9.915,14.245) CW10(7.427,14.053) CW33(-3.828,14.305) CY3(10.89,14.808) CY4(10.24,14.808) CY6(9.189,14.511) CY7(8.539,14.511) CY9(7.889,14.511) CY11(6.965,14.511) CY32(-3.366,14.762) CY34(-4.29,14.762) CY35(-4.94,14.762) CY37(-5.59,14.762) CY38(-6.24,14.762) CY39(-6.89,14.762) CY41(-7.54,14.762) CY42(-8.19,14.762) CY43(-8.84,14.762) CY45(-9.59,14.527) CY46(-10.241,14.527) D2(11.22,-22.522) D4(10.381,-22.459) D7(8.658,-22.415) D8(8.095,-22.74) D9(7.532,-22.415) D12(6.184,-22.415) D13(5.621,-22.74) D14(5.058,-22.415) D33(-3.593,-22.415) D35(-4.795,-22.415) D36(-5.424,-22.741) D38(-6.077,-22.415) D40(-7.383,-22.415) D42(-8.036,-22.741) D43(-8.707,-22.415) D44(-9.354,-22.492) D47(-10.866,-22.545) D49(-11.865,-22.605) DA3(10.565,15.371) DA5(9.915,15.371) DA6(9.189,15.426) DA7(8.539,15.426) DA9(7.889,15.426) DA10(7.427,14.968) DA11(6.965,15.426) DA33(-3.828,15.22) DA45(-9.915,15.158) DA47(-10.565,15.158) DB10(7.427,15.883) DB32(-3.366,15.677) DB34(-4.29,15.677) DB35(-4.94,15.677) DB37(-5.59,15.677) DB38(-6.24,15.677) DB39(-6.89,15.677) DB41(-7.54,15.677) DB42(-8.19,15.677) DB43(-8.84,15.677) DB45(-9.59,15.778) DB47(-10.861,15.778) DC3(10.893,16.045) DC5(9.905,16.045) DC6(9.189,16.341) DC7(8.539,16.341) DC9(7.889,16.341) DC11(6.965,16.341) DC33(-3.828,16.135) DC45(-9.915,16.398) DC47(-10.565,16.398) DD3(10.565,16.719) DD5(9.915,16.719) DD34(-4.29,16.592) DD35(-4.94,16.592) DD37(-5.59,16.592) DD38(-6.24,16.592) DD39(-6.89,16.592) DD41(-7.54,16.592) DD42(-8.19,16.592) DD43(-8.84,16.592) DE3(10.89,17.282) DE4(10.24,17.282) DE6(9.189,17.256) DE7(8.539,17.256) DE9(7.889,17.256) DE10(7.239,17.256) DE45(-9.59,17.029) DE46(-10.241,17.029) DF3(10.565,17.845) DF5(9.915,17.845) DF34(-4.29,17.507) DF35(-4.94,17.507) DF37(-5.59,17.507) DF38(-6.24,17.507) DF39(-6.89,17.507) DF41(-7.54,17.507) DF42(-8.19,17.507) DF43(-8.84,17.507) DF45(-9.915,17.66) DF47(-10.565,17.66) DG6(9.189,18.171) DG7(8.539,18.171) DG9(7.889,18.171) DG10(7.239,18.171) DG34(-4.476,18.332) DG36(-5.391,18.332) DG38(-6.306,18.332) DG40(-7.221,18.332) DG42(-8.136,18.332) DG44(-9.051,18.332) DG47(-10.861,18.288) DH3(10.893,18.519) DH5(9.905,18.519) DH45(-9.915,18.871) DH47(-10.565,18.871) DJ3(10.565,19.193) DJ5(9.915,19.193) DJ6(9.249,18.982) DJ8(8.334,18.982) DJ10(7.419,18.982) DJ11(6.504,18.982) DJ13(5.589,18.982) DJ15(4.674,18.982) DJ17(3.759,18.982) DJ19(2.844,18.982) DJ21(1.929,18.982) DJ22(1.014,18.982) DJ24(0.099,18.982) DJ27(-0.816,18.982) DJ29(-1.731,18.982) DJ31(-2.646,18.982) DJ33(-3.561,18.982) DJ34(-4.476,18.982) DJ36(-5.391,18.982) DJ38(-6.306,18.982) DJ40(-7.221,18.982) DJ42(-8.136,18.982) DJ44(-9.051,18.982) DK3(10.89,19.756) DK4(10.24,19.756) DK6(9.249,19.632) DK8(8.334,19.632) DK10(7.419,19.632) DK11(6.504,19.632) DK13(5.589,19.632) DK15(4.674,19.632) DK17(3.759,19.632) DK19(2.844,19.632) DK21(1.929,19.632) DK22(1.014,19.632) DK24(0.099,19.632) DK27(-0.816,19.632) DK29(-1.731,19.632) DK31(-2.646,19.632) DK33(-3.561,19.632) DK34(-4.476,19.632) DK36(-5.391,19.632) DK38(-6.306,19.632) DK40(-7.221,19.632) DK42(-8.136,19.632) DK44(-9.051,19.632) DK46(-10.24,19.524) DL3(10.565,20.319) DL5(9.915,20.319) DL6(9.249,20.282) DL8(8.334,20.282) DL10(7.419,20.282) DL11(6.504,20.282) DL13(5.589,20.282) DL15(4.674,20.282) DL17(3.759,20.282) DL19(2.844,20.282) DL21(1.929,20.282) DL22(1.014,20.282) DL24(0.099,20.282) DL27(-0.816,20.282) DL29(-1.731,20.282) DL31(-2.646,20.282) DL33(-3.561,20.282) DL34(-4.476,20.282) DL36(-5.391,20.282) DL38(-6.306,20.282) DL40(-7.221,20.282) DL42(-8.136,20.282) DL44(-9.051,20.282) DL45(-9.915,20.177) DL47(-10.565,20.177) DN3(10.893,20.993) DN5(9.905,20.993) DN6(9.249,20.932) DN8(8.334,20.932) DN10(7.419,20.932) DN11(6.504,20.932) DN13(5.589,20.932) DN15(4.674,20.932) DN17(3.759,20.932) DN19(2.844,20.932) DN21(1.929,20.932) DN22(1.014,20.932) DN24(0.099,20.932) DN27(-0.816,20.932) DN29(-1.731,20.932) DN31(-2.646,20.932) DN33(-3.561,20.932) DN34(-4.476,20.932) DN36(-5.391,20.932) DN38(-6.306,20.932) DN40(-7.221,20.932) DN42(-8.136,20.932) DN44(-9.051,20.932) DN47(-10.565,21.305) DP1(11.865,21.667) DP3(10.565,21.667) DP5(9.915,21.667) DP6(9.249,21.582) DP8(8.334,21.582) DP10(7.419,21.582) DP11(6.504,21.582) DP13(5.589,21.582) DP15(4.674,21.582) DP17(3.759,21.582) DP19(2.844,21.582) DP21(1.929,21.582) DP22(1.014,21.582) DP24(0.099,21.582) DP27(-0.816,21.582) DP29(-1.731,21.582) DP31(-2.646,21.582) DP33(-3.561,21.582) DP34(-4.476,21.582) DP36(-5.391,21.582) DP38(-6.306,21.582) DP40(-7.221,21.582) DP42(-8.136,21.582) DP44(-9.051,21.582) DP45(-9.915,21.629) DR5(9.948,22.316) DR47(-10.565,21.955) DR48(-11.215,21.955) DR49(-11.865,21.955) DT1(11.865,22.605) DT2(11.237,22.437) DT3(10.587,22.437) DT6(9.306,22.415) DT7(8.67,22.74) DT8(8.017,22.415) DT10(7.36,22.415) DT11(6.703,22.415) DT12(6.05,22.74) DT14(5.397,22.415) DT15(4.74,22.415) DT16(4.083,22.415) DT18(3.43,22.74) DT19(2.777,22.415) DT20(2.12,22.415) DT22(1.463,22.415) DT23(0.81,22.74) DT24(0.157,22.415) DT27(-0.5,22.415) DT28(-1.157,22.415) DT29(-1.81,22.74) DT30(-2.463,22.415) DT32(-3.12,22.415) DT33(-3.777,22.415) DT34(-4.43,22.74) DT36(-5.083,22.415) DT37(-5.74,22.415) DT38(-6.397,22.415) DT40(-7.05,22.74) DT41(-7.703,22.415) DT42(-8.36,22.415) DT44(-9.026,22.416) DT45(-9.676,22.48) DT47(-10.906,22.527) DT49(-11.865,22.605) DU2(11.237,23.087) DU3(10.587,23.087) DU6(9.323,23.065) DU10(7.36,23.39) DU15(4.74,23.39) DU20(2.12,23.39) DU27(-0.5,23.39) DU32(-3.12,23.39) DU37(-5.74,23.39) DU42(-8.36,23.39) DU44(-9.026,23.066) DU45(-9.676,23.13) DU47(-10.566,23.084) DU48(-11.236,23.087) DV3(10.587,23.737) DV4(10.023,23.41) DV6(9.426,23.715) DV44(-9.026,23.716) DV45(-9.936,23.733) DV47(-10.586,23.734) DW4(10.105,24.365) DW6(9.426,24.365) DW44(-9.026,24.366) DW46(-10.105,24.365) E1(11.865,-21.955) E3(10.836,-21.994) E5(9.87,-22.002) E6(9.332,-22.4) E11(6.858,-22.4) E16(4.384,-22.4) E34(-4.176,-22.091) E36(-5.424,-22.091) E39(-6.73,-22.091) E42(-8.036,-22.091) E46(-10.226,-22.394) E48(-11.43,-22.101) F6(9.282,-21.697) F8(8.367,-21.697) F10(7.452,-21.697) F11(6.537,-21.697) F13(5.622,-21.697) F15(4.707,-21.697) F17(3.728,-21.765) F33(-3.593,-21.765) F45(-9.59,-21.874) F47(-10.809,-21.89) G1(11.542,-21.379) G3(10.893,-21.346) G5(9.905,-21.346) G6(9.282,-21.047) G8(8.367,-21.047) G10(7.452,-21.047) G11(6.537,-21.047) G13(5.622,-21.047) G15(4.707,-21.047) G17(3.728,-21.115) G33(-3.593,-21.115) G34(-4.404,-21.344) G36(-5.319,-21.344) G38(-6.24,-21.173) G39(-6.89,-21.173) G41(-7.54,-21.173) G42(-8.19,-21.173) G43(-8.84,-21.173) G45(-9.915,-21.259) G47(-10.565,-21.259) G48(-11.215,-21.314) G49(-11.865,-21.314) H1(11.865,-20.671) H3(10.565,-20.671) H5(9.915,-20.671) H17(3.728,-20.465) H33(-3.593,-20.465) H34(-4.404,-20.694) H36(-5.319,-20.694) H45(-9.59,-20.641) H46(-10.24,-20.641) J3(10.89,-20.108) J4(10.24,-20.108) J6(9.282,-20.397) J8(8.367,-20.397) J10(7.452,-20.397) J11(6.537,-20.397) J13(5.622,-20.397) J15(4.707,-20.397) J16(4.185,-20.003) J18(3.27,-20.003) J20(2.355,-20.003) J22(1.44,-20.003) J23(0.525,-20.003) J26(-0.39,-20.003) J28(-1.305,-20.003) J30(-2.22,-20.003) J32(-3.135,-20.003) J34(-4.404,-20.044) J36(-5.319,-20.044) J38(-6.24,-20.258) J39(-6.89,-20.258) J41(-7.54,-20.258) J42(-8.19,-20.258) J43(-8.84,-20.258) J45(-9.915,-19.988) J47(-10.565,-19.988) K3(10.565,-19.545) K5(9.915,-19.545) K6(9.282,-19.747) K8(8.367,-19.747) K10(7.452,-19.747) K11(6.537,-19.747) K13(5.622,-19.747) K15(4.643,-19.541) K17(3.728,-19.541) K19(2.813,-19.541) K21(1.898,-19.541) K23(0.983,-19.541) K24(0.068,-19.541) K27(-0.848,-19.541) K29(-1.763,-19.541) K31(-2.678,-19.541) K33(-3.593,-19.541) L6(9.282,-19.097) L8(8.367,-19.097) L10(7.452,-19.097) L11(6.537,-19.097) L13(5.622,-19.097) L34(-4.404,-19.394) L36(-5.319,-19.394) L38(-6.24,-19.343) L39(-6.89,-19.343) L41(-7.54,-19.343) L42(-8.19,-19.343) L43(-8.84,-19.343) L45(-9.59,-19.335) L47(-10.861,-19.335) M3(10.893,-18.871) M5(9.905,-18.871) M6(9.282,-18.447) M8(8.367,-18.447) M10(7.452,-18.447) M11(6.537,-18.447) M13(5.622,-18.447) M34(-4.404,-18.744) M36(-5.319,-18.744) M38(-6.24,-18.428) M39(-6.89,-18.428) M41(-7.54,-18.428) M42(-8.19,-18.428) M43(-8.84,-18.428) M45(-9.915,-18.682) M47(-10.565,-18.682) N3(10.565,-18.197) N5(9.915,-18.197) N34(-4.404,-18.094) N36(-5.319,-18.094) N45(-9.59,-18.029) N46(-10.24,-18.029) P3(10.89,-17.634) P4(10.24,-17.634) P6(9.282,-17.797) P8(8.367,-17.797) P10(7.452,-17.797) P11(6.537,-17.797) P13(5.622,-17.797) P38(-6.24,-17.513) P39(-6.89,-17.513) P41(-7.54,-17.513) P42(-8.19,-17.513) P43(-8.84,-17.513) R3(10.565,-17.071) R5(9.915,-17.071) R12(6.127,-17.057) R35(-4.855,-17.056) R37(-5.778,-17.056) R45(-9.915,-17.376) R47(-10.565,-17.376) T6(9.189,-16.6) T7(8.539,-16.6) T9(7.889,-16.6) T10(7.239,-16.6) T11(6.589,-16.6) T13(5.665,-16.6) T34(-4.393,-16.598) T36(-5.316,-16.598) T38(-6.24,-16.598) T39(-6.89,-16.598) T41(-7.54,-16.598) T42(-8.19,-16.598) T43(-8.84,-16.598) T45(-9.59,-16.748) T47(-10.861,-16.748) U3(10.893,-16.397) U5(9.905,-16.397) U12(6.127,-16.142) U35(-4.855,-16.141) U37(-5.778,-16.141) U45(-9.915,-16.128) U47(-10.565,-16.128) V3(10.565,-15.723) V5(9.915,-15.723) V6(9.189,-15.685) V7(8.539,-15.685) V9(7.889,-15.685) V10(7.239,-15.685) V11(6.589,-15.685) V13(5.665,-15.685) V34(-4.393,-15.683) V36(-5.316,-15.683) V38(-6.24,-15.683) V39(-6.89,-15.683) V41(-7.54,-15.683) V42(-8.19,-15.683) V43(-8.84,-15.683) V45(-9.59,-15.497) V46(-10.241,-15.497) W3(10.89,-15.16) W4(10.24,-15.16) W12(6.127,-15.227) W35(-4.855,-15.226) W37(-5.778,-15.226) Y3(10.565,-14.597) Y5(9.915,-14.597) Y6(9.189,-14.77) Y7(8.539,-14.77) Y9(7.889,-14.77) Y10(7.239,-14.77) Y11(6.589,-14.77) Y13(5.665,-14.77) Y34(-4.393,-14.768) Y36(-5.316,-14.768) Y38(-6.24,-14.768) Y39(-6.89,-14.768) Y41(-7.54,-14.768) Y42(-8.19,-14.768) Y43(-8.84,-14.768) Y45(-9.915,-14.866) Y47(-10.565,-14.866)
  oval 0.254x0.33 smd: A9(7.532,-24.365) A11(6.858,-24.043) A12(6.184,-24.365) A14(5.058,-24.365) A16(4.384,-24.043) A36(-5.424,-24.041) A38(-6.077,-24.365) A39(-6.73,-24.041) A40(-7.383,-24.365) A42(-8.036,-24.041) B9(7.532,-23.715) B12(6.184,-23.715) B14(5.058,-23.715) B38(-6.077,-23.715) B40(-7.383,-23.715) C36(-5.424,-23.391) C42(-8.036,-23.391) DU7(8.67,23.39) DU8(8.017,23.065) DU11(6.703,23.065) DU12(6.05,23.39) DU14(5.397,23.065) DU16(4.083,23.065) DU18(3.43,23.39) DU19(2.777,23.065) DU22(1.463,23.065) DU23(0.81,23.39) DU24(0.157,23.065) DU28(-1.157,23.065) DU29(-1.81,23.39) DU30(-2.463,23.065) DU33(-3.777,23.065) DU34(-4.43,23.39) DU36(-5.083,23.065) DU38(-6.397,23.065) DU40(-7.05,23.39) DU41(-7.703,23.065) DV8(8.017,23.715) DV11(6.703,23.715) DV14(5.397,23.715) DV16(4.083,23.715) DV19(2.777,23.715) DV22(1.463,23.715) DV24(0.157,23.715) DV28(-1.157,23.715) DV30(-2.463,23.715) DV33(-3.777,23.715) DV36(-5.083,23.715) DV38(-6.397,23.715) DV41(-7.703,23.715) DW7(8.67,24.04) DW8(8.017,24.365) DW10(7.36,24.04) DW11(6.703,24.365) DW12(6.05,24.04) DW14(5.397,24.365) DW15(4.74,24.04) DW16(4.083,24.365) DW18(3.43,24.04) DW19(2.777,24.365) DW20(2.12,24.04) DW22(1.463,24.365) DW23(0.81,24.04) DW24(0.157,24.365) DW27(-0.5,24.04) DW28(-1.157,24.365) DW29(-1.81,24.04) DW30(-2.463,24.365) DW32(-3.12,24.04) DW33(-3.777,24.365) DW34(-4.43,24.04) DW36(-5.083,24.365) DW37(-5.74,24.04) DW38(-6.397,24.365) DW40(-7.05,24.04) DW41(-7.703,24.365) DW42(-8.36,24.04)
  round 0.406 smd: A17(3.728,-24.365) A19(2.813,-24.365) A21(1.898,-24.365) A23(0.983,-24.365) A24(0.068,-24.365) A27(-0.848,-24.365) A29(-1.763,-24.365) A31(-2.678,-24.365) B17(3.728,-23.715) B19(2.813,-23.715) B21(1.898,-23.715) B23(0.983,-23.715) B24(0.068,-23.715) B27(-0.848,-23.715) B29(-1.763,-23.715) B31(-2.678,-23.715) C17(3.728,-23.065) C19(2.813,-23.065) C21(1.898,-23.065) C23(0.983,-23.065) C24(0.068,-23.065) C27(-0.848,-23.065) C29(-1.763,-23.065) C31(-2.678,-23.065) D17(3.728,-22.415) D19(2.813,-22.415) D21(1.898,-22.415) D23(0.983,-22.415) D24(0.068,-22.415) D27(-0.848,-22.415) D29(-1.763,-22.415) D31(-2.678,-22.415) F19(2.813,-21.765) F21(1.898,-21.765) F23(0.983,-21.765) F24(0.068,-21.765) F27(-0.848,-21.765) F29(-1.763,-21.765) F31(-2.678,-21.765) G19(2.813,-21.115) G21(1.898,-21.115) G23(0.983,-21.115) G24(0.068,-21.115) G27(-0.848,-21.115) G29(-1.763,-21.115) G31(-2.678,-21.115) H19(2.813,-20.465) H21(1.898,-20.465) H23(0.983,-20.465) H24(0.068,-20.465) H27(-0.848,-20.465) H29(-1.763,-20.465) H31(-2.678,-20.465)
  oval 0.203x0.305 smd: A34(-4.176,-24.011) A35(-4.795,-24.365) B35(-4.795,-23.715)
  oval 0.305x0.203 smd: AA49(-11.511,-14.246) AB48(-11.215,-13.626) AB49(-11.865,-13.626) AC47(-10.891,-12.995) AC49(-11.541,-12.995) AE48(-11.215,-12.364) AE49(-11.865,-12.364) AF49(-11.511,-11.744) AG48(-11.215,-11.124) AG49(-11.865,-11.124) AH1(11.865,-10.706) AH2(11.215,-10.706) AH47(-10.891,-10.493) AH49(-11.541,-10.493) AJ1(11.865,-10.056) AJ2(11.215,-10.056) AK48(-11.215,-9.862) AK49(-11.865,-9.862) AL1(11.865,-9.406) AL2(11.215,-9.406) AL49(-11.511,-9.242) AM1(11.865,-8.756) AM2(11.215,-8.756) AM48(-11.215,-8.622) AM49(-11.865,-8.622) AN1(11.865,-8.106) AN2(11.215,-8.106) AN47(-10.891,-7.991) AN49(-11.541,-7.991) AR1(11.865,-7.456) AR2(11.215,-7.456) AR48(-11.215,-7.36) AR49(-11.865,-7.36) AT1(11.865,-6.806) AT2(11.215,-6.806) AT49(-11.511,-6.74) AU1(11.865,-6.156) AU2(11.215,-6.156) AU48(-11.215,-6.12) AU49(-11.865,-6.12) AV1(11.865,-5.506) AV2(11.215,-5.506) AV47(-10.891,-5.489) AV49(-11.541,-5.489) AY1(11.865,-4.856) AY2(11.215,-4.856) AY48(-11.215,-4.858) AY49(-11.865,-4.858) BA1(11.865,-4.206) BA2(11.215,-4.206) BA49(-11.511,-4.238) BB1(11.865,-3.556) BB2(11.215,-3.556) BB48(-11.215,-3.618) BB49(-11.865,-3.618) BD1(11.865,-2.906) BD2(11.215,-2.906) BD47(-10.891,-2.987) BD49(-11.541,-2.987) BE1(11.865,-2.256) BE2(11.215,-2.256) BE48(-11.215,-2.356) BE49(-11.865,-2.356) BF1(11.865,-1.606) BF2(11.215,-1.606) BF49(-11.511,-1.736) BG48(-11.215,-1.116) BG49(-11.865,-1.116) BH1(11.865,-0.956) BH2(11.215,-0.956) BJ1(11.865,-0.306) BJ2(11.215,-0.306) BJ47(-10.891,-0.485) BJ49(-11.541,-0.485) BL1(11.865,0.344) BL2(11.215,0.344) BL48(-11.215,0.146) BL49(-11.865,0.146) BM1(11.865,0.994) BM2(11.215,0.994) BM49(-11.511,0.766) BN48(-11.215,1.386) BN49(-11.865,1.386) BP1(11.865,1.644) BP2(11.215,1.644) BR1(11.865,2.294) BR2(11.215,2.294) BR47(-10.891,2.017) BR49(-11.541,2.017) BT1(11.865,2.944) BT2(11.215,2.944) BT48(-11.215,2.648) BT49(-11.865,2.648) BU49(-11.511,3.268) BV1(11.865,3.594) BV2(11.215,3.594) BV48(-11.215,3.888) BV49(-11.865,3.888) BW1(11.865,4.244) BW2(11.215,4.244) BY1(11.865,4.894) BY2(11.215,4.894) BY47(-10.891,4.519) BY49(-11.541,4.519) CA48(-11.215,5.15) CA49(-11.865,5.15) CB1(11.865,5.544) CB2(11.215,5.544) CB49(-11.511,5.77) CC48(-11.215,6.39) CC49(-11.865,6.39) CE47(-10.891,7.021) CE49(-11.541,7.021) CF48(-11.215,7.652) CF49(-11.865,7.652) CG49(-11.511,8.272) CH48(-11.215,8.892) CH49(-11.865,8.892) CK47(-10.891,9.523) CK49(-11.541,9.523) CL48(-11.215,10.154) CL49(-11.865,10.154) CM49(-11.511,10.774) CN48(-11.215,11.394) CN49(-11.865,11.394) CR47(-10.891,12.025) CR49(-11.541,12.025) CT48(-11.215,12.656) CT49(-11.865,12.656) CU49(-11.511,13.276) CV48(-11.215,13.896) CV49(-11.865,13.896) CY47(-10.891,14.527) CY49(-11.541,14.527) DA48(-11.215,15.158) DA49(-11.865,15.158) DB49(-11.511,15.778) DC48(-11.215,16.398) DC49(-11.865,16.398) DE47(-10.891,17.029) DE49(-11.541,17.029) DF48(-11.215,17.66) DF49(-11.865,17.66) T49(-11.511,-16.748) U48(-11.215,-16.128) U49(-11.865,-16.128) V47(-10.891,-15.497) V49(-11.541,-15.497) Y48(-11.215,-14.866) Y49(-11.865,-14.866)
  oval 0.33x0.254 smd: AB1(11.543,-13.923) AC1(11.865,-13.249) AC2(11.215,-13.249) AE1(11.865,-12.123) AE2(11.215,-12.123) AG1(11.543,-11.449) CC1(11.543,6.149) CD1(11.865,6.823) CD2(11.215,6.823) CF1(11.865,7.949) CF2(11.215,7.949) CH1(11.543,8.623) CJ1(11.865,9.297) CJ2(11.215,9.297) CL1(11.865,10.423) CL2(11.215,10.423) CN1(11.543,11.097) CP1(11.865,11.771) CP2(11.215,11.771) CT1(11.865,12.897) CT2(11.215,12.897) CV1(11.543,13.571) CW1(11.865,14.245) CW2(11.215,14.245) DA1(11.865,15.371) DA2(11.215,15.371) DC1(11.543,16.045) DD1(11.865,16.719) DD2(11.215,16.719) DF1(11.865,17.845) DF2(11.215,17.845) DG49(-11.511,18.288) DH1(11.543,18.519) DH48(-11.215,18.871) DH49(-11.865,18.871) DJ1(11.865,19.193) DJ2(11.215,19.193) DK47(-10.89,19.524) DK49(-11.54,19.524) DL1(11.865,20.319) DL2(11.215,20.319) DL48(-11.215,20.177) DL49(-11.865,20.177) DM47(-10.89,20.741) DM49(-11.54,20.741) DN1(11.543,20.993) DN48(-11.215,21.305) DN49(-11.865,21.305) DP2(11.215,21.667) H2(11.215,-20.671) H47(-10.89,-20.641) H49(-11.54,-20.641) J48(-11.215,-19.988) J49(-11.865,-19.988) K1(11.865,-19.545) K2(11.215,-19.545) L49(-11.54,-19.335) M1(11.543,-18.871) M48(-11.215,-18.682) M49(-11.865,-18.682) N1(11.865,-18.197) N2(11.215,-18.197) N47(-10.89,-18.029) N49(-11.54,-18.029) R1(11.865,-17.071) R2(11.215,-17.071) R48(-11.215,-17.376) R49(-11.865,-17.376) U1(11.543,-16.397) V1(11.865,-15.723) V2(11.215,-15.723) Y1(11.865,-14.597) Y2(11.215,-14.597)
